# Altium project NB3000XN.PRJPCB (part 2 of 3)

## Sheet FPGA_NonIO.SchDoc: USER FPGA Pwr and Programming
size A4; Organization: Altium Limited.; Address1: Level 3, 12a Rodborough Rd; Address2: Frenchs Forest 2086; Address3: NSW; Address4: AUSTRALIA; DocumentNumber: 8; SheetNumber: 9; SheetTotal: 78
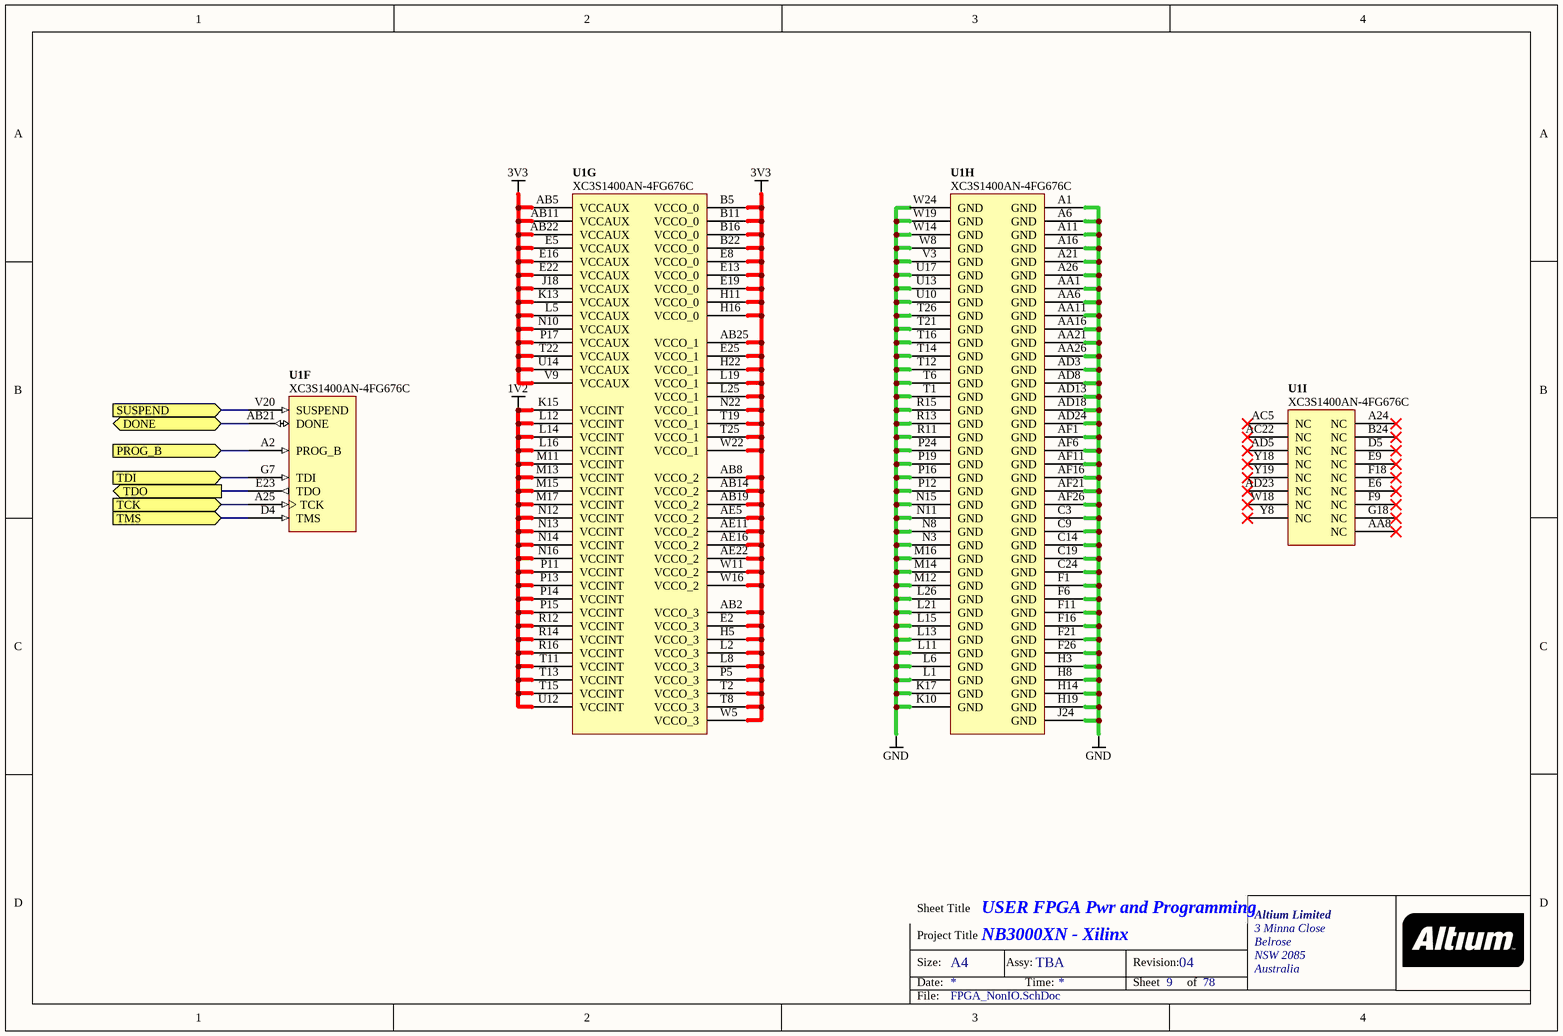
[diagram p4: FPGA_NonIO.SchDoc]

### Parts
(Parts that share a designator on the sheet are numbered #1, #2 ... from top to bottom, then left to right.)
U1#1  XC3S1400AN-4FG676C  [BGA100P26X26-676]  (parts F,G,H,I of 9)

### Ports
DONE (bidir), PROG_B (in), SUSPEND (in), TCK (in), TDI (in), TDO (out), TMS (in)

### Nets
1V2: U1#1.K15(VCCINT) U1#1.L12(VCCINT) U1#1.L14(VCCINT) U1#1.L16(VCCINT) U1#1.M11(VCCINT) U1#1.M13(VCCINT) U1#1.M15(VCCINT) U1#1.M17(VCCINT) U1#1.N12(VCCINT) U1#1.N13(VCCINT) U1#1.N14(VCCINT) U1#1.N16(VCCINT) U1#1.P11(VCCINT) U1#1.P13(VCCINT) U1#1.P14(VCCINT) U1#1.P15(VCCINT) U1#1.R12(VCCINT) U1#1.R14(VCCINT) U1#1.R16(VCCINT) U1#1.T11(VCCINT) U1#1.T13(VCCINT) U1#1.T15(VCCINT) U1#1.U12(VCCINT)
3V3: U1#1.AB2(VCCO_3) U1#1.AB5(VCCAUX) U1#1.AB8(VCCO_2) U1#1.AB11(VCCAUX) U1#1.AB14(VCCO_2) U1#1.AB19(VCCO_2) U1#1.AB22(VCCAUX) U1#1.AB25(VCCO_1) U1#1.AE5(VCCO_2) U1#1.AE11(VCCO_2) U1#1.AE16(VCCO_2) U1#1.AE22(VCCO_2) U1#1.B5(VCCO_0) U1#1.B11(VCCO_0) U1#1.B16(VCCO_0) U1#1.B22(VCCO_0) U1#1.E2(VCCO_3) U1#1.E5(VCCAUX) U1#1.E8(VCCO_0) U1#1.E13(VCCO_0) U1#1.E16(VCCAUX) U1#1.E19(VCCO_0) U1#1.E22(VCCAUX) U1#1.E25(VCCO_1) U1#1.H5(VCCO_3) U1#1.H11(VCCO_0) U1#1.H16(VCCO_0) U1#1.H22(VCCO_1) U1#1.J18(VCCAUX) U1#1.K13(VCCAUX) U1#1.L2(VCCO_3) U1#1.L5(VCCAUX) U1#1.L8(VCCO_3) U1#1.L19(VCCO_1) U1#1.L25(VCCO_1) U1#1.N10(VCCAUX) U1#1.N22(VCCO_1) U1#1.P5(VCCO_3) U1#1.P17(VCCAUX) U1#1.T2(VCCO_3) U1#1.T8(VCCO_3) U1#1.T19(VCCO_1) U1#1.T22(VCCAUX) U1#1.T25(VCCO_1) U1#1.U14(VCCAUX) U1#1.V9(VCCAUX) U1#1.W5(VCCO_3) U1#1.W11(VCCO_2) U1#1.W16(VCCO_2) U1#1.W22(VCCO_1)
GND: U1#1.A1(GND) U1#1.A6(GND) U1#1.A11(GND) U1#1.A16(GND) U1#1.A21(GND) U1#1.A26(GND) U1#1.AA1(GND) U1#1.AA6(GND) U1#1.AA11(GND) U1#1.AA16(GND) U1#1.AA21(GND) U1#1.AA26(GND) U1#1.AD3(GND) U1#1.AD8(GND) U1#1.AD13(GND) U1#1.AD18(GND) U1#1.AD24(GND) U1#1.AF1(GND) U1#1.AF6(GND) U1#1.AF11(GND) U1#1.AF16(GND) U1#1.AF21(GND) U1#1.AF26(GND) U1#1.C3(GND) U1#1.C9(GND) U1#1.C14(GND) U1#1.C19(GND) U1#1.C24(GND) U1#1.F1(GND) U1#1.F6(GND) U1#1.F11(GND) U1#1.F16(GND) U1#1.F21(GND) U1#1.F26(GND) U1#1.H3(GND) U1#1.H8(GND) U1#1.H14(GND) U1#1.H19(GND) U1#1.J24(GND) U1#1.K10(GND) U1#1.K17(GND) U1#1.L1(GND) U1#1.L6(GND) U1#1.L11(GND) U1#1.L13(GND) U1#1.L15(GND) U1#1.L21(GND) U1#1.L26(GND) U1#1.M12(GND) U1#1.M14(GND) U1#1.M16(GND) U1#1.N3(GND) U1#1.N8(GND) U1#1.N11(GND) U1#1.N15(GND) U1#1.P12(GND) U1#1.P16(GND) U1#1.P19(GND) U1#1.P24(GND) U1#1.R11(GND) U1#1.R13(GND) U1#1.R15(GND) U1#1.T1(GND) U1#1.T6(GND) U1#1.T12(GND) U1#1.T14(GND) U1#1.T16(GND) U1#1.T21(GND) U1#1.T26(GND) U1#1.U10(GND) U1#1.U13(GND) U1#1.U17(GND) U1#1.V3(GND) U1#1.V20(SUSPEND) U1#1.W8(GND) U1#1.W14(GND) U1#1.W19(GND) U1#1.W24(GND) ; port SUSPEND
DONE: U1#1.AB21(DONE) ; port DONE
PROG_B: U1#1.A2(PROG_B) ; port PROG_B
TCK: U1#1.A25(TCK) ; port TCK
TDI: U1#1.G7(TDI) ; port TDI
TDO: U1#1.E23(TDO) ; port TDO
TMS: U1#1.D4(TMS) ; port TMS

Not connected (* = marked no-connect by the designer): U1#1 A24(NC)* AA8(NC)* AC5(NC)* AC22(NC)* AD5(NC)* AD23(NC)* B24(NC)* D5(NC)* E6(NC)* E9(NC)* F9(NC)* F18(NC)* G18(NC)* W18(NC)* Y8(NC)* Y18(NC)* Y19(NC)*

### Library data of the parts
U1#1 = D-241-0015: FPGA, Xilinx Spartan 3AN-1400 FG676; Supply Voltage: mV

## Sheet FPGA_Bypass_1V2.SCHDOC: FPGA Bypass 1V2
size A4; Organization: Altium Limited.; Address1: Level 3, 12a Rodborough Rd; Address2: Frenchs Forest 2086; Address3: NSW; Address4: AUSTRALIA; DocumentNumber: 60; SheetNumber: 61; SheetTotal: 78; PageSetup: Record=PageOptions|CenterHorizontal=True|CenterVertical=True|PrintScale=0.97|XCorrection=1.00|YCorrection=1.00|PrintKind=0|BorderSize=5000000|LeftOffset=0|BottomOffset=0|Orientation=2|PaperLength=1000|PaperWidth=1000|Scale=100|PaperSource=7|PrintQuality=-4|MediaType=1|DitherType=10|PaperKind=A4 (210 x 297 mm)|PrintScaleMode=1
Used 2 times, as channels FPGA_USER/USER_DECOUPLING_CAPS_1V2, FPGA_HOST/HOST_DECOUPLING_CAPS_1V2. Parts and nets are listed once, with the designators drawn on the sheet.
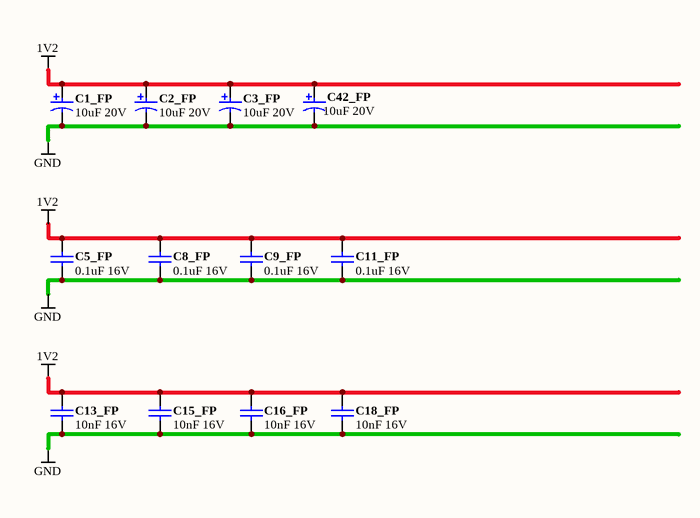
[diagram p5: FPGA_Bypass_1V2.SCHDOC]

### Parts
C1_FP  10uF 20V  [CAPC3528-STAR]
C2_FP  10uF 20V  [CAPC3528-STAR]
C3_FP  10uF 20V  [CAPC3528-STAR]
C5_FP  0.1uF 16V  [CAPC1005-STAR]
C8_FP  0.1uF 16V  [CAPC1005-STAR]
C9_FP  0.1uF 16V  [CAPC1005-STAR]
C11_FP  0.1uF 16V  [CAPC1005-STAR]
C13_FP  10nF 16V  [CAPC1005-STAR]
C15_FP  10nF 16V  [CAPC1005-STAR]
C16_FP  10nF 16V  [CAPC1005-STAR]
C18_FP  10nF 16V  [CAPC1005-STAR]
C42_FP  10uF 20V  [CAPC3528-STAR]

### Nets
1V2: C1_FP.1 C2_FP.1 C3_FP.1 C5_FP.1 C8_FP.1 C9_FP.1 C11_FP.1 C13_FP.1 C15_FP.1 C16_FP.1 C18_FP.1 C42_FP.1
GND: C1_FP.2 C2_FP.2 C3_FP.2 C5_FP.2 C8_FP.2 C9_FP.2 C11_FP.2 C13_FP.2 C15_FP.2 C16_FP.2 C18_FP.2 C42_FP.2

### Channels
FPGA_USER/USER_DECOUPLING_CAPS_1V2: designators end in A
FPGA_HOST/HOST_DECOUPLING_CAPS_1V2: designators end in B

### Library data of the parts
C1_FP C2_FP C3_FP C42_FP = D-101-0007: Capacitor, Tantalum, 10uF 10% 20V MCCT-B (3528); Polarity: Polarized
C5_FP C8_FP C9_FP C11_FP = D-101-0080: Capacitor, Ceramic, 0.1uF 10% 16V 0402 (1005) X7R; Polarity: Non-Polarized
C13_FP C15_FP C16_FP C18_FP = D-101-0077: Capacitor, Ceramic, 10nF 10% 16V 0402 (1005) X7R; Polarity: Non-Polarized

## Sheet FPGA_Bypass_3V3.SCHDOC: FPGA Bypass 3V3
size A4; Organization: Altium Limited.; Address1: Level 3, 12a Rodborough Rd; Address2: Frenchs Forest 2086; Address3: NSW; Address4: AUSTRALIA; DocumentNumber: 58; SheetNumber: 59; SheetTotal: 78; PageSetup: Record=PageOptions|CenterHorizontal=True|CenterVertical=True|PrintScale=0.97|XCorrection=1.00|YCorrection=1.00|PrintKind=0|BorderSize=5000000|LeftOffset=0|BottomOffset=0|Orientation=2|PaperLength=1000|PaperWidth=1000|Scale=100|PaperSource=7|PrintQuality=-4|MediaType=1|DitherType=10|PaperKind=A4 (210 x 297 mm)|PrintScaleMode=1
Used 2 times, as channels FPGA_USER/USER_DECOUPLING_CAPS_3V3, FPGA_HOST/HOST_DECOUPLING_CAPS_3V3. Parts and nets are listed once, with the designators drawn on the sheet.
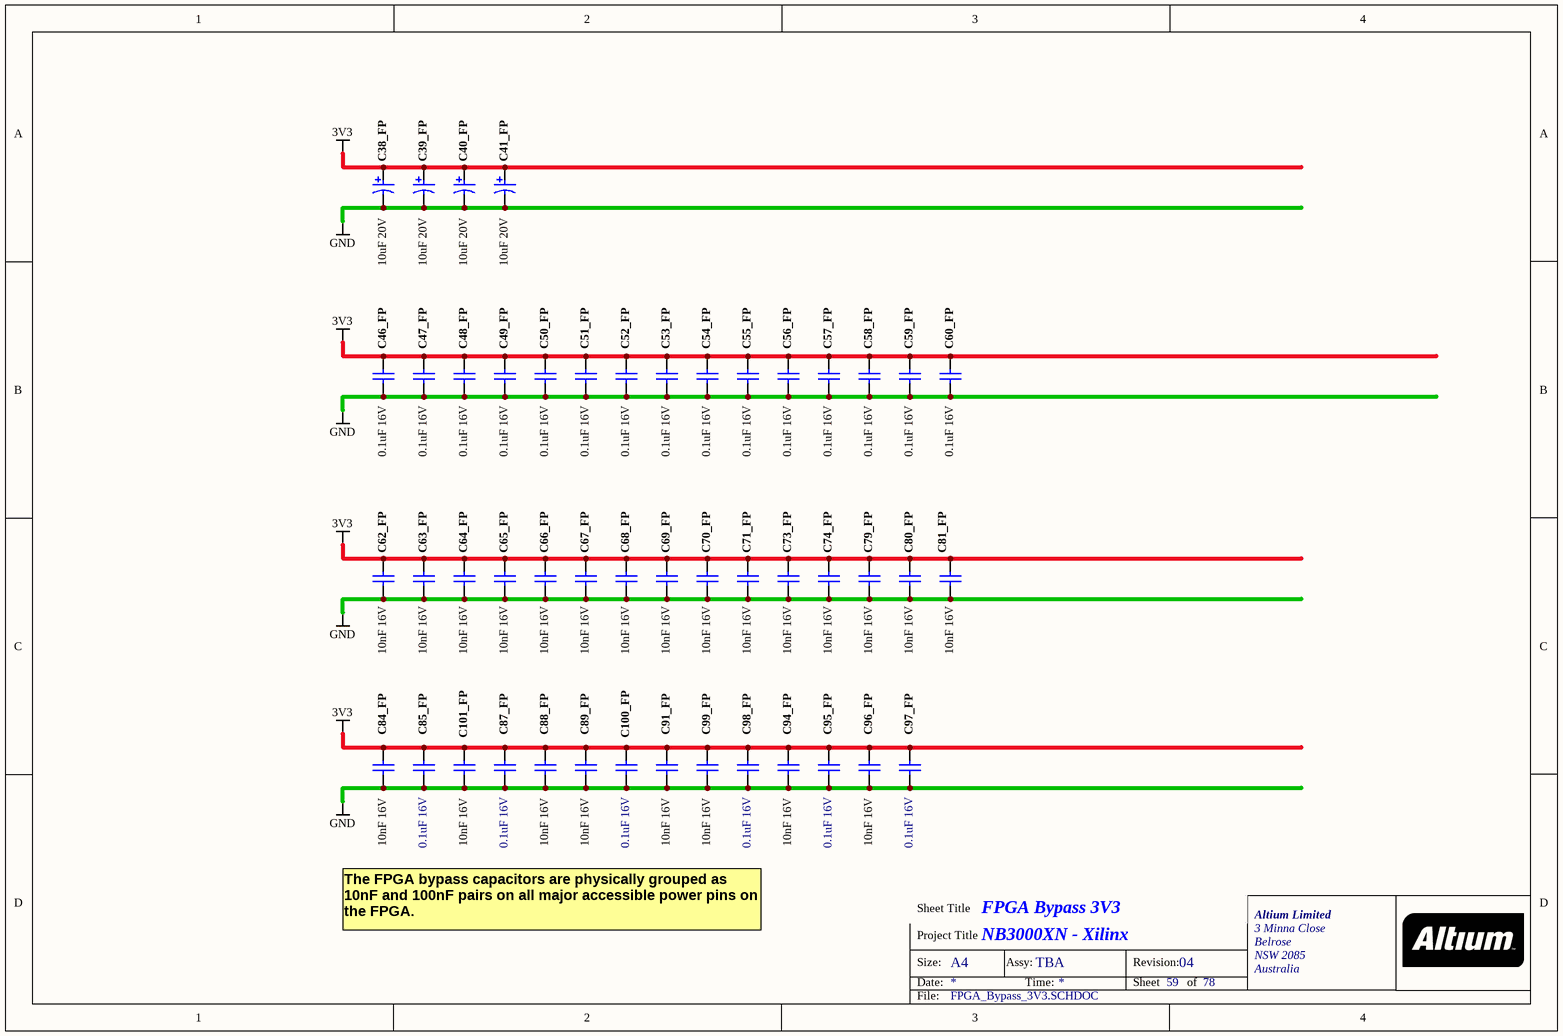
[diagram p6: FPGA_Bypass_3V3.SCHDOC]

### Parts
C38_FP  10uF 20V  [CAPC3528-STAR]
C39_FP  10uF 20V  [CAPC3528-STAR]
C40_FP  10uF 20V  [CAPC3528-STAR]
C41_FP  10uF 20V  [CAPC3528-STAR]
C46_FP  0.1uF 16V  [CAPC1005-STAR]
C47_FP  0.1uF 16V  [CAPC1005-STAR]
C48_FP  0.1uF 16V  [CAPC1005-STAR]
C49_FP  0.1uF 16V  [CAPC1005-STAR]
C50_FP  0.1uF 16V  [CAPC1005-STAR]
C51_FP  0.1uF 16V  [CAPC1005-STAR]
C52_FP  0.1uF 16V  [CAPC1005-STAR]
C53_FP  0.1uF 16V  [CAPC1005-STAR]
C54_FP  0.1uF 16V  [CAPC1005-STAR]
C55_FP  0.1uF 16V  [CAPC1005-STAR]
C56_FP  0.1uF 16V  [CAPC1005-STAR]
C57_FP  0.1uF 16V  [CAPC1005-STAR]
C58_FP  0.1uF 16V  [CAPC1005-STAR]
C59_FP  0.1uF 16V  [CAPC1005-STAR]
C60_FP  0.1uF 16V  [CAPC1005-STAR]
C62_FP  10nF 16V  [CAPC1005-STAR]
C63_FP  10nF 16V  [CAPC1005-STAR]
C64_FP  10nF 16V  [CAPC1005-STAR]
C65_FP  10nF 16V  [CAPC1005-STAR]
C66_FP  10nF 16V  [CAPC1005-STAR]
C67_FP  10nF 16V  [CAPC1005-STAR]
C68_FP  10nF 16V  [CAPC1005-STAR]
C69_FP  10nF 16V  [CAPC1005-STAR]
C70_FP  10nF 16V  [CAPC1005-STAR]
C71_FP  10nF 16V  [CAPC1005-STAR]
C73_FP  10nF 16V  [CAPC1005-STAR]
C74_FP  10nF 16V  [CAPC1005-STAR]
C79_FP  10nF 16V  [CAPC1005-STAR]
C80_FP  10nF 16V  [CAPC1005-STAR]
C81_FP  10nF 16V  [CAPC1005-STAR]
C84_FP  10nF 16V  [CAPC1005-STAR]
C85_FP  0.1uF 16V  [CAPC1005-STAR]
C87_FP  0.1uF 16V  [CAPC1005-STAR]
C88_FP  10nF 16V  [CAPC1005-STAR]
C89_FP  10nF 16V  [CAPC1005-STAR]
C91_FP  10nF 16V  [CAPC1005-STAR]
C94_FP  10nF 16V  [CAPC1005-STAR]
C95_FP  0.1uF 16V  [CAPC1005-STAR]
C96_FP  10nF 16V  [CAPC1005-STAR]
C97_FP  0.1uF 16V  [CAPC1005-STAR]
C98_FP  0.1uF 16V  [CAPC1005-STAR]
C99_FP  10nF 16V  [CAPC1005-STAR]
C100_FP  0.1uF 16V  [CAPC1005-STAR]
C101_FP  10nF 16V  [CAPC1005-STAR]

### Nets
3V3: C38_FP.1 C39_FP.1 C40_FP.1 C41_FP.1 C46_FP.1 C47_FP.1 C48_FP.1 C49_FP.1 C50_FP.1 C51_FP.1 C52_FP.1 C53_FP.1 C54_FP.1 C55_FP.1 C56_FP.1 C57_FP.1 C58_FP.1 C59_FP.1 C60_FP.1 C62_FP.1 C63_FP.1 C64_FP.1 C65_FP.1 C66_FP.1 C67_FP.1 C68_FP.1 C69_FP.1 C70_FP.1 C71_FP.1 C73_FP.1 C74_FP.1 C79_FP.1 C80_FP.1 C81_FP.1 C84_FP.1 C85_FP.1 C87_FP.1 C88_FP.1 C89_FP.1 C91_FP.1 C94_FP.1 C95_FP.1 C96_FP.1 C97_FP.1 C98_FP.1 C99_FP.1 C100_FP.1 C101_FP.1
GND: C38_FP.2 C39_FP.2 C40_FP.2 C41_FP.2 C46_FP.2 C47_FP.2 C48_FP.2 C49_FP.2 C50_FP.2 C51_FP.2 C52_FP.2 C53_FP.2 C54_FP.2 C55_FP.2 C56_FP.2 C57_FP.2 C58_FP.2 C59_FP.2 C60_FP.2 C62_FP.2 C63_FP.2 C64_FP.2 C65_FP.2 C66_FP.2 C67_FP.2 C68_FP.2 C69_FP.2 C70_FP.2 C71_FP.2 C73_FP.2 C74_FP.2 C79_FP.2 C80_FP.2 C81_FP.2 C84_FP.2 C85_FP.2 C87_FP.2 C88_FP.2 C89_FP.2 C91_FP.2 C94_FP.2 C95_FP.2 C96_FP.2 C97_FP.2 C98_FP.2 C99_FP.2 C100_FP.2 C101_FP.2

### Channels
FPGA_USER/USER_DECOUPLING_CAPS_3V3: designators end in A
FPGA_HOST/HOST_DECOUPLING_CAPS_3V3: designators end in B

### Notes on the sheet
- The FPGA bypass capacitors are physically grouped as 10nF and 100nF pairs on all major accessible power pins on the FPGA.

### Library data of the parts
C38_FP C39_FP C40_FP C41_FP = D-101-0007: as C1_FP on sheet FPGA_Bypass_1V2
C46_FP C47_FP C48_FP C49_FP C50_FP C51_FP C52_FP C53_FP C54_FP C55_FP C56_FP C57_FP C58_FP C59_FP C60_FP C85_FP C87_FP C95_FP C97_FP C98_FP C100_FP = D-101-0080: as C5_FP on sheet FPGA_Bypass_1V2
C62_FP C63_FP C64_FP C65_FP C66_FP C67_FP C68_FP C69_FP C70_FP C71_FP C73_FP C74_FP C79_FP C80_FP C81_FP C84_FP C88_FP C89_FP C91_FP C94_FP C96_FP C99_FP C101_FP = D-101-0077: as C13_FP on sheet FPGA_Bypass_1V2

## Sheet VGA_OUT.SCHDOC: VGA Ouput
size A4; DocumentNumber: 2; SheetNumber: 3; SheetTotal: 78; PageSetup: Record=PageOptions|CenterHorizontal=True|CenterVertical=True|PrintScale=0.97|XCorrection=1.00|YCorrection=1.00|PrintKind=1|BorderSize=5000000|LeftOffset=0|BottomOffset=0|Orientation=2|PaperLength=1000|PaperWidth=1000|Scale=100|PaperSource=7|PrintQuality=-4|MediaType=1|DitherType=10|PaperKind=A4 (210 x 297 mm)|PrintScaleMode=1
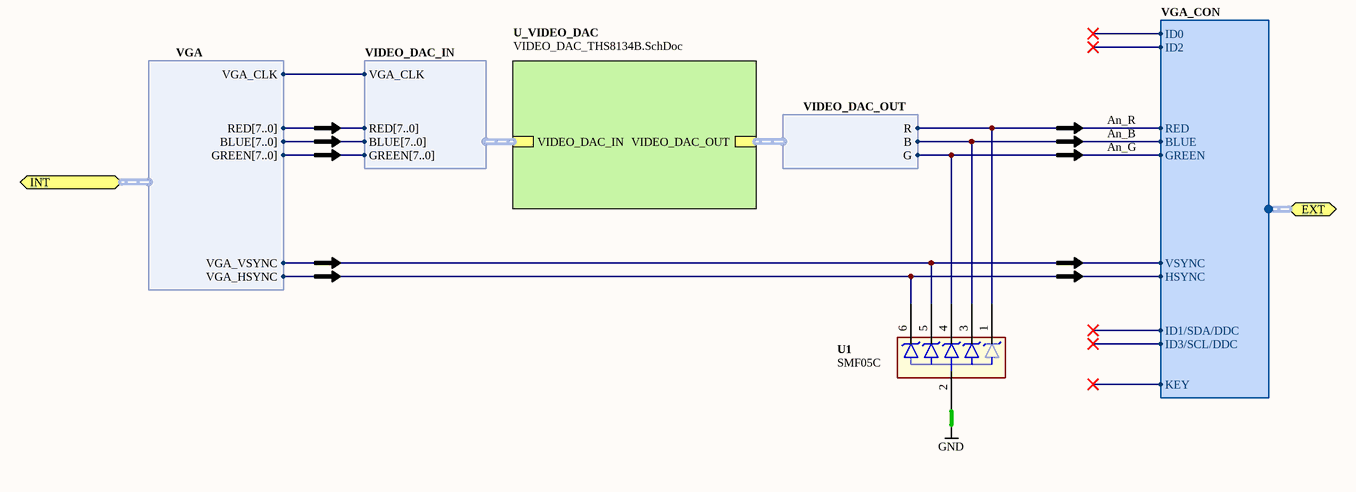
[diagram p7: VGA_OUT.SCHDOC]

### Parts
(Parts that share a designator on the sheet are numbered #1, #2 ... from top to bottom, then left to right.)
U1#2  SMF05C  [SC70_6L]

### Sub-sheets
U_VIDEO_DAC = VIDEO_DAC_THS8134B.SchDoc: VIDEO_DAC_OUT (harness VIDEO_DAC_OUT), VIDEO_DAC_IN (harness VIDEO_DAC_IN)

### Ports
EXT (harness VGA_CON), INT (harness VGA)

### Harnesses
VIDEO_DAC_IN: RED[7..0], GREEN[7..0], BLUE[7..0], VGA_CLK
VIDEO_DAC_OUT: B, R, G
VGA: RED[7..0], GREEN[7..0], BLUE[7..0], VGA_CLK, VGA_VSYNC, VGA_HSYNC
VGA_CON: RED, GREEN, BLUE, VSYNC, HSYNC, KEY, ID2, ID3/SCL/DDC, ID1/SDA/DDC, ID0

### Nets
GND: U1#2.2
An_B: U1#2.3 ; sheet U_VIDEO_DAC/VIDEO_DAC_OUT.B, port EXT.BLUE  [project net VGA#.BLUE]
An_G: U1#2.4 ; sheet U_VIDEO_DAC/VIDEO_DAC_OUT.G, port EXT.GREEN  [project net VGA#.GREEN]
An_R: U1#2.1 ; sheet U_VIDEO_DAC/VIDEO_DAC_OUT.R, port EXT.RED  [project net VGA#.RED]
VGA#.HSYNC: U1#2.6 ; port INT.VGA_HSYNC, port EXT.HSYNC
VGA#.VSYNC: U1#2.5 ; port INT.VGA_VSYNC, port EXT.VSYNC
VGA.VGA_CLK: sheet U_VIDEO_DAC/VIDEO_DAC_IN.VGA_CLK, port INT.VGA_CLK

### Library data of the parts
U1#2 = D-157-0000: TVS Diode Array  For ESD and Latch-Up Protection; Junction Capacitance: 130 pF; Peak Pulse Current: 8 A; Peak Pulse Power: 100 W; Reverse Breakdown Voltage: 6 V

## Sheet VIDEO_DAC_THS8134B.SchDoc: Video DAC
size A4; Organization: Altium Limited.; Address1: Level 3, 12a Rodborough Rd; Address2: Frenchs Forest 2086; Address3: NSW; Address4: AUSTRALIA; DocumentNumber: 62; SheetNumber: 63; SheetTotal: 78
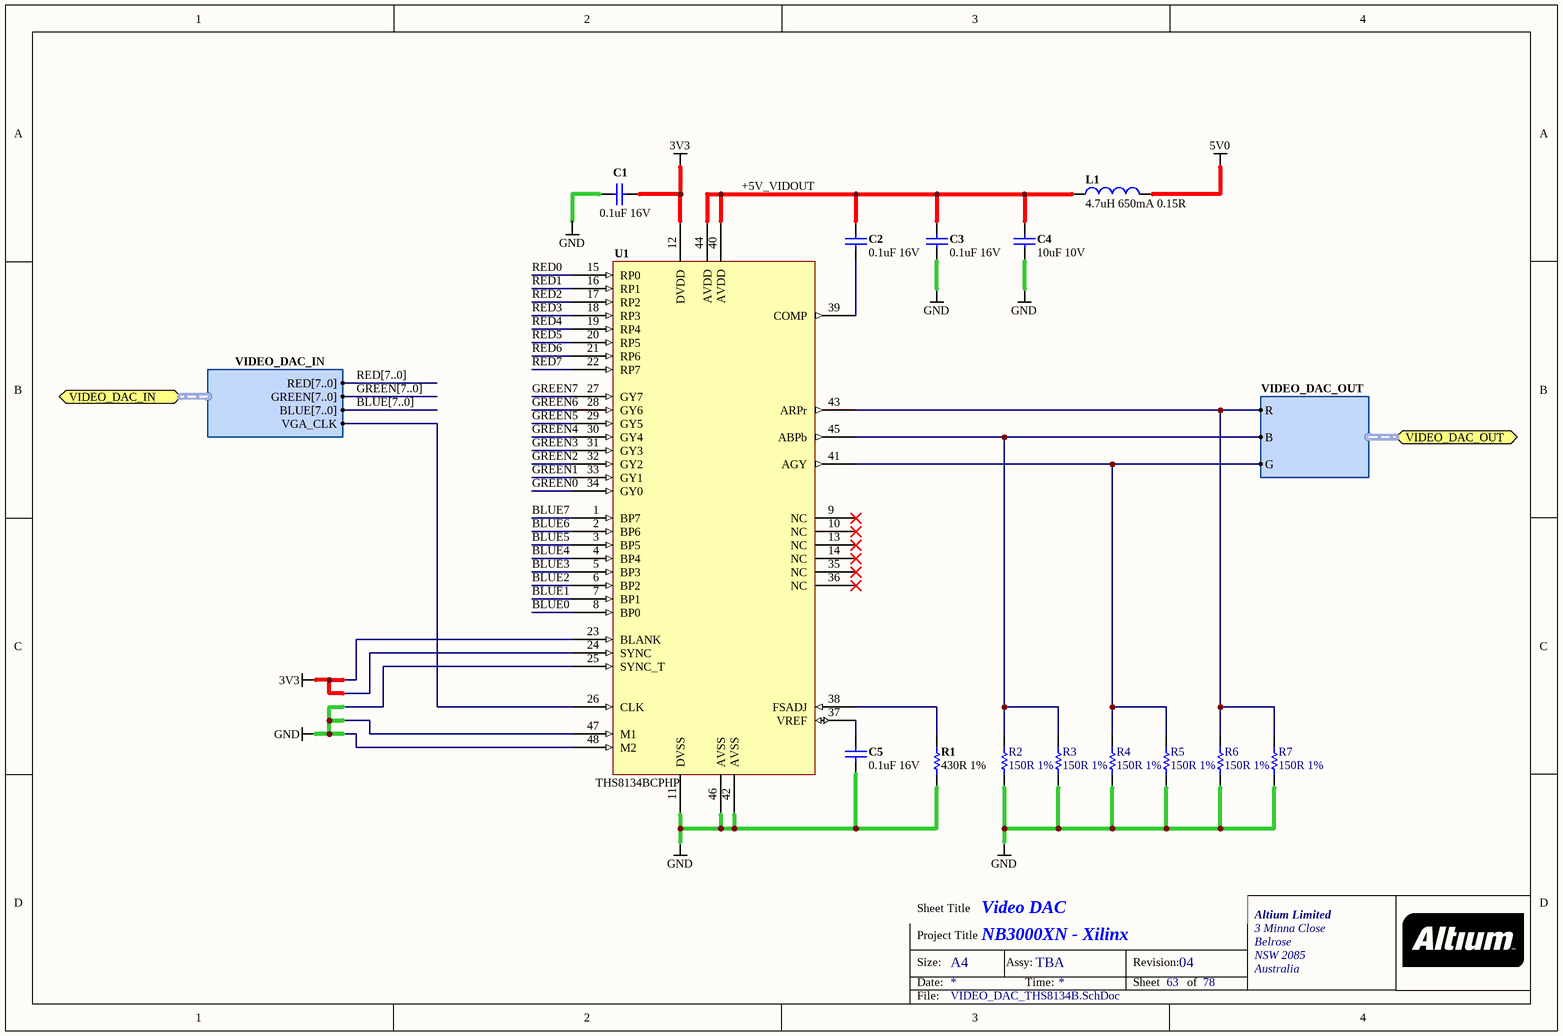
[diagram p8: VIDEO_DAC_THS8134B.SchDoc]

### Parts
(Parts that share a designator on the sheet are numbered #1, #2 ... from top to bottom, then left to right.)
C1#2  0.1uF 16V  [CAPC1005-STAR]
C2#2  0.1uF 16V  [CAPC1005-STAR]
C3#2  0.1uF 16V  [CAPC1005-STAR]
C4#2  10uF 10V  [CAPC2012-STAR]
C5#1  0.1uF 16V  [CAPC1005-STAR]
L1#1  4.7uH 650mA 0.15R  [INDC3225]
R1#2  430R 1%  [RESC1005-STAR]
R2#2  150R 1%  [RESC1005-STAR]
R3#2  150R 1%  [RESC1005-STAR]
R4#2  150R 1%  [RESC1005-STAR]
R5#1  150R 1%  [RESC1005-STAR]
R6#1  150R 1%  [RESC1005-STAR]
R7#1  150R 1%  [RESC1005-STAR]
U1#3  THS8134BCPHP  [TSQFP50P900X900_HS-48]

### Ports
VIDEO_DAC_IN (harness VIDEO_DAC_IN), VIDEO_DAC_OUT (harness VIDEO_DAC_OUT)

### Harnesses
VIDEO_DAC_OUT: B, R, G
VIDEO_DAC_IN: RED[7..0], GREEN[7..0], BLUE[7..0], VGA_CLK

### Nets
3V3: C1#2.1 U1#3.12(DVDD) U1#3.23(BLANK) U1#3.24(SYNC)
5V0: L1#1.1
GND: C1#2.2 C3#2.2 C4#2.1 C5#1.2 R1#2.1 R2#2.2 R3#2.1 R4#2.2 R5#1.1 R6#1.1 R7#1.1 U1#3.11(DVSS) U1#3.25(SYNC_T) U1#3.42(AVSS) U1#3.46(AVSS) U1#3.47(M1) U1#3.48(M2)
+5V_VIDOUT: C2#2.1 C3#2.1 C4#2.2 L1#1.2 U1#3.40(AVDD) U1#3.44(AVDD)
BLUE0: U1#3.8(BP0)  [project net VGA_BLUE0]
BLUE1: U1#3.7(BP1)  [project net VGA_BLUE1]
BLUE2: U1#3.6(BP2)  [project net VGA_BLUE2]
BLUE3: U1#3.5(BP3)  [project net VGA_BLUE3]
BLUE4: U1#3.4(BP4)  [project net VGA_BLUE4]
BLUE5: U1#3.3(BP5)  [project net VGA_BLUE5]
BLUE6: U1#3.2(BP6)  [project net VGA_BLUE6]
BLUE7: U1#3.1(BP7)  [project net VGA_BLUE7]
GREEN0: U1#3.34(GY0)  [project net VGA_GREEN0]
GREEN1: U1#3.33(GY1)  [project net VGA_GREEN1]
GREEN2: U1#3.32(GY2)  [project net VGA_GREEN2]
GREEN3: U1#3.31(GY3)  [project net VGA_GREEN3]
GREEN4: U1#3.30(GY4)  [project net VGA_GREEN4]
GREEN5: U1#3.29(GY5)  [project net VGA_GREEN5]
GREEN6: U1#3.28(GY6)  [project net VGA_GREEN6]
GREEN7: U1#3.27(GY7)  [project net VGA_GREEN7]
RED0: U1#3.15(RP0)  [project net VGA_RED0]
RED1: U1#3.16(RP1)  [project net VGA_RED1]
RED2: U1#3.17(RP2)  [project net VGA_RED2]
RED3: U1#3.18(RP3)  [project net VGA_RED3]
RED4: U1#3.19(RP4)  [project net VGA_RED4]
RED5: U1#3.20(RP5)  [project net VGA_RED5]
RED6: U1#3.21(RP6)  [project net VGA_RED6]
RED7: U1#3.22(RP7)  [project net VGA_RED7]
VGA#.BLUE: R2#2.1 R3#2.2 U1#3.45(ABPb) ; port VIDEO_DAC_OUT.B
VGA#.GREEN: R4#2.1 R5#1.2 U1#3.41(AGY) ; port VIDEO_DAC_OUT.G
VGA#.RED: R6#1.2 R7#1.2 U1#3.43(ARPr) ; port VIDEO_DAC_OUT.R
VGA.VGA_CLK: U1#3.26(CLK) ; port VIDEO_DAC_IN.VGA_CLK
NetC2#2_2: C2#2.2 U1#3.39(COMP)
NetC5#1_1: C5#1.1 U1#3.37(VREF)
NetR1#2_2: R1#2.2 U1#3.38(FSADJ)

Not connected (* = marked no-connect by the designer): U1#3 9(NC)* 10(NC)* 13(NC)* 14(NC)* 35(NC)* 36(NC)*

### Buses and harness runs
bus BLUE[7..0]
bus GREEN[7..0]
bus RED[7..0]

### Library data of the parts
C1#2 C2#2 C3#2 C5#1 = D-101-0080: as C5_FP on sheet FPGA_Bypass_1V2
C4#2 = D-101-0087: Capacitor, Ceramic, 10uF 10% 10V 0805 (2012) X5R; Polarity: Non-Polarized
L1#1 = D-102-0005: Inductor, 4.7uH 650mA 0.15R 1210 (3225) LQH32CN4R7M11L
R1#2 = D-100-0096: Resistor, 430R 1% 0402 (1005); Power Rating: 63 mW
R2#2 R3#2 R4#2 R5#1 R6#1 R7#1 = D-100-0005: Resistor, 150R 1% 0402 (1005); Power Rating: 63mW
U1#3 = D-222-0000: THS8134BCPHP, Triple 8-Bit, 80 MSPS Video DAC with Tri-Level Sync Generation

## Sheet Host_FPGA.SchDoc: Host Controller - Spartan3AN-400
size A2; Organization: Altium Limited.; Address1: Level 3, 12a Rodborough Rd; Address2: Frenchs Forest 2086; Address3: NSW; Address4: AUSTRALIA; DocumentNumber: 28; Revision: 6; SheetNumber: 29; SheetTotal: 78; PageSetup: Record=PageOptions|CenterHorizontal=True|CenterVertical=True|PrintScale=0.47|XCorrection=1.00|YCorrection=1.00|PrintKind=0|BorderSize=5000000|LeftOffset=0|BottomOffset=0|Orientation=2|PaperLength=1000|PaperWidth=1000|Scale=100|PaperSource=7|PrintQuality=1200|MediaType=1|DitherType=10|PaperKind=A4 (210 x 297 mm)|PrintScaleMode=1
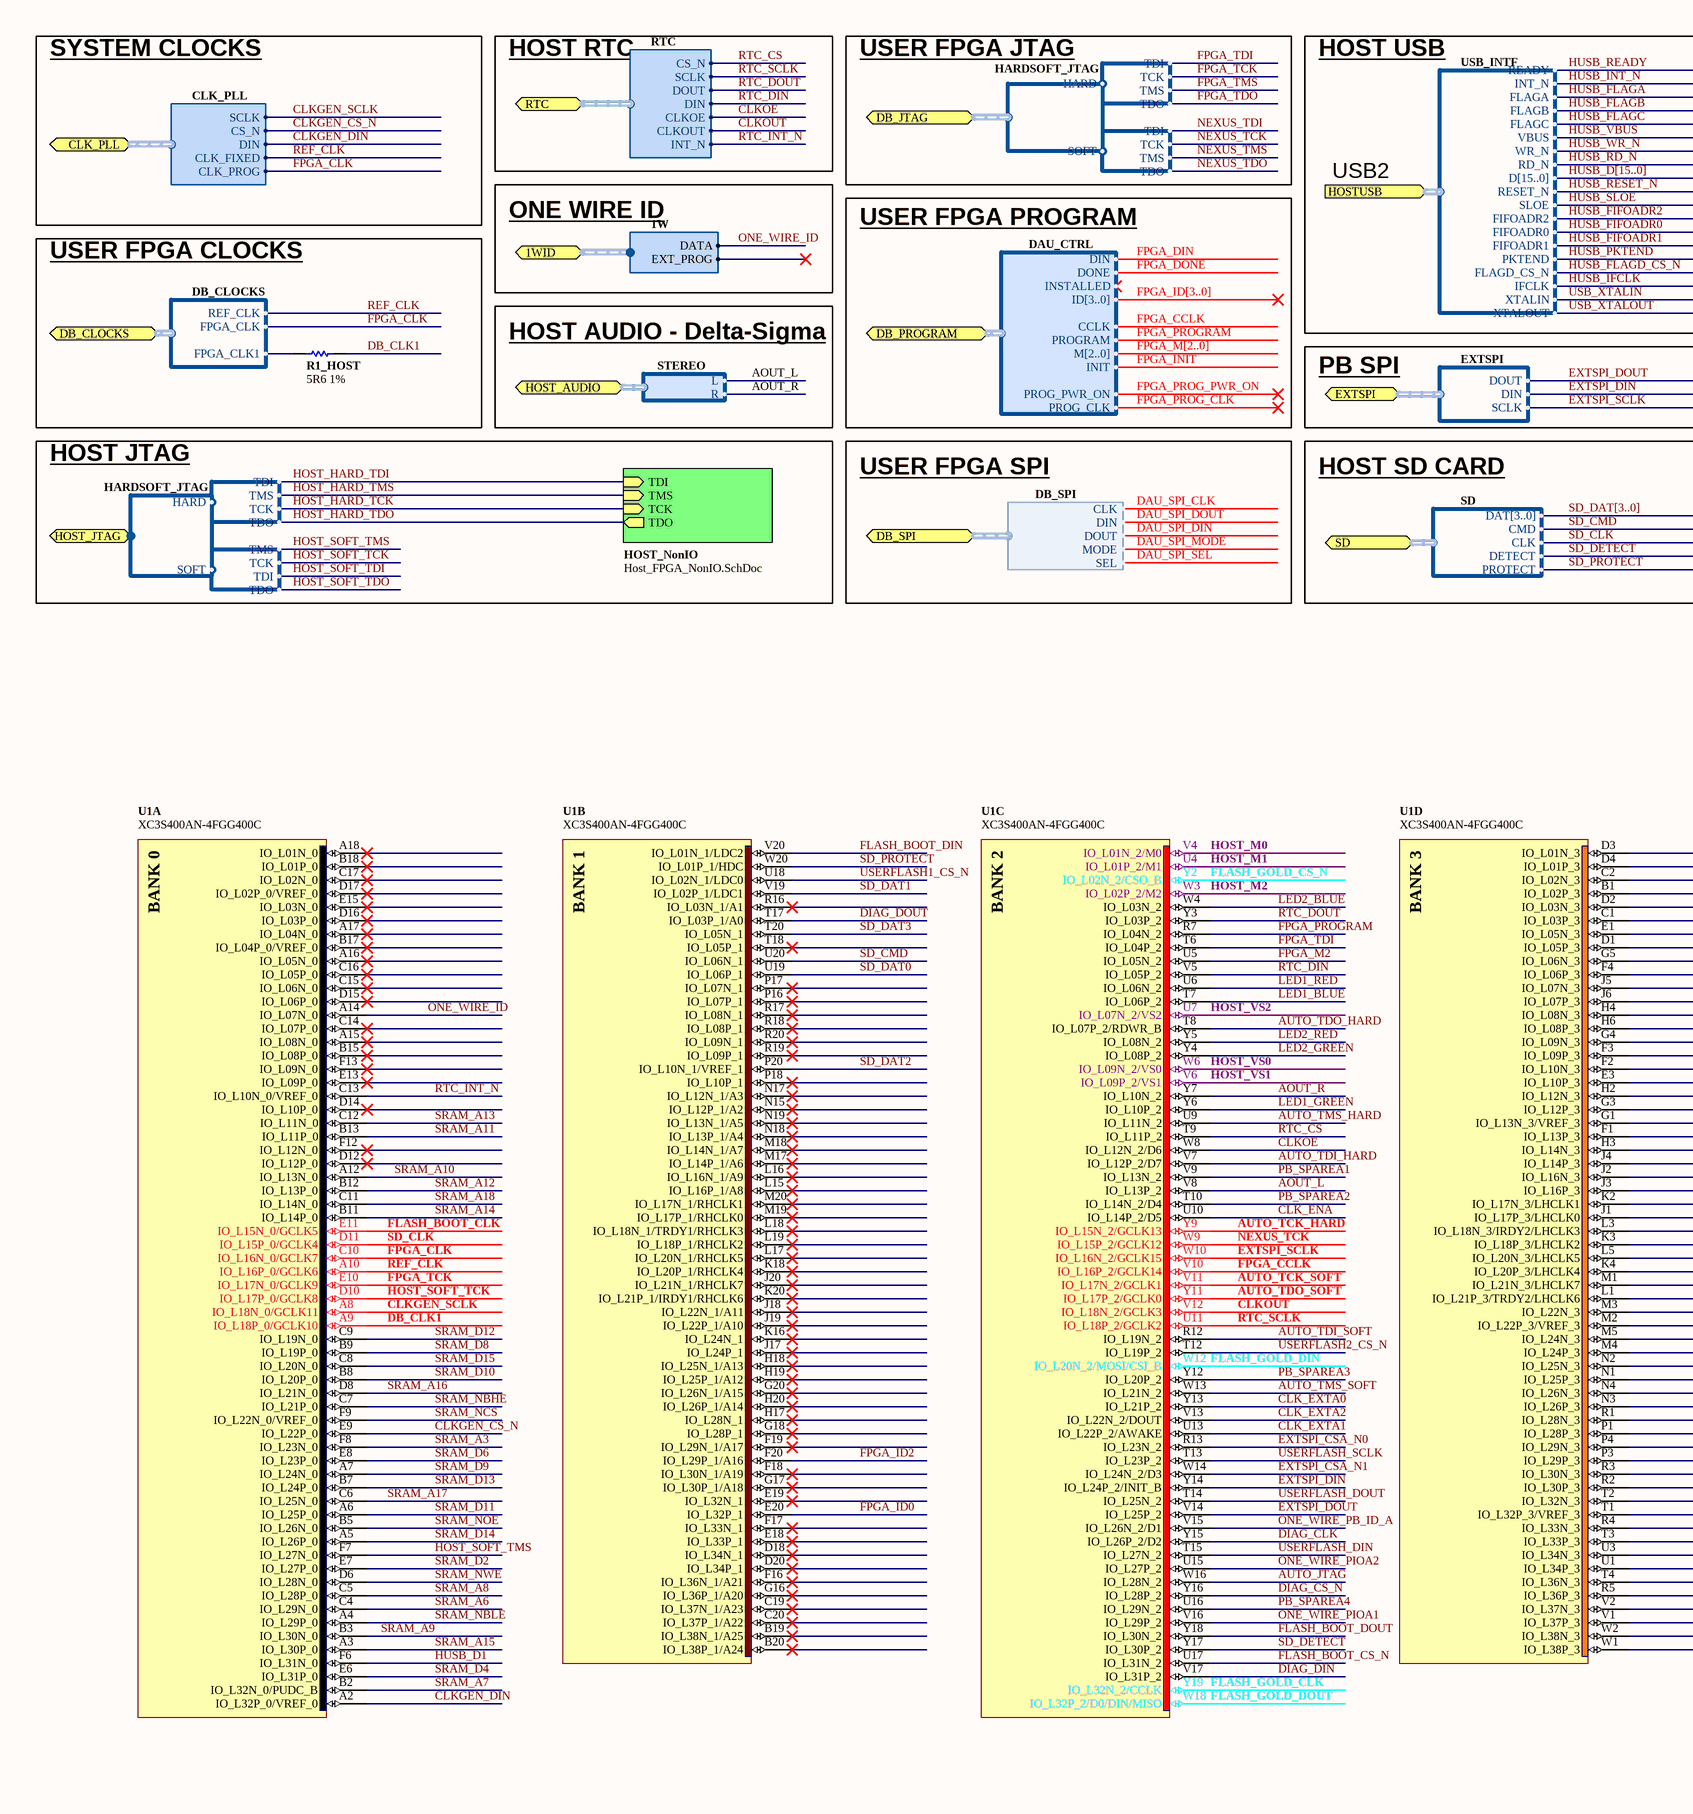
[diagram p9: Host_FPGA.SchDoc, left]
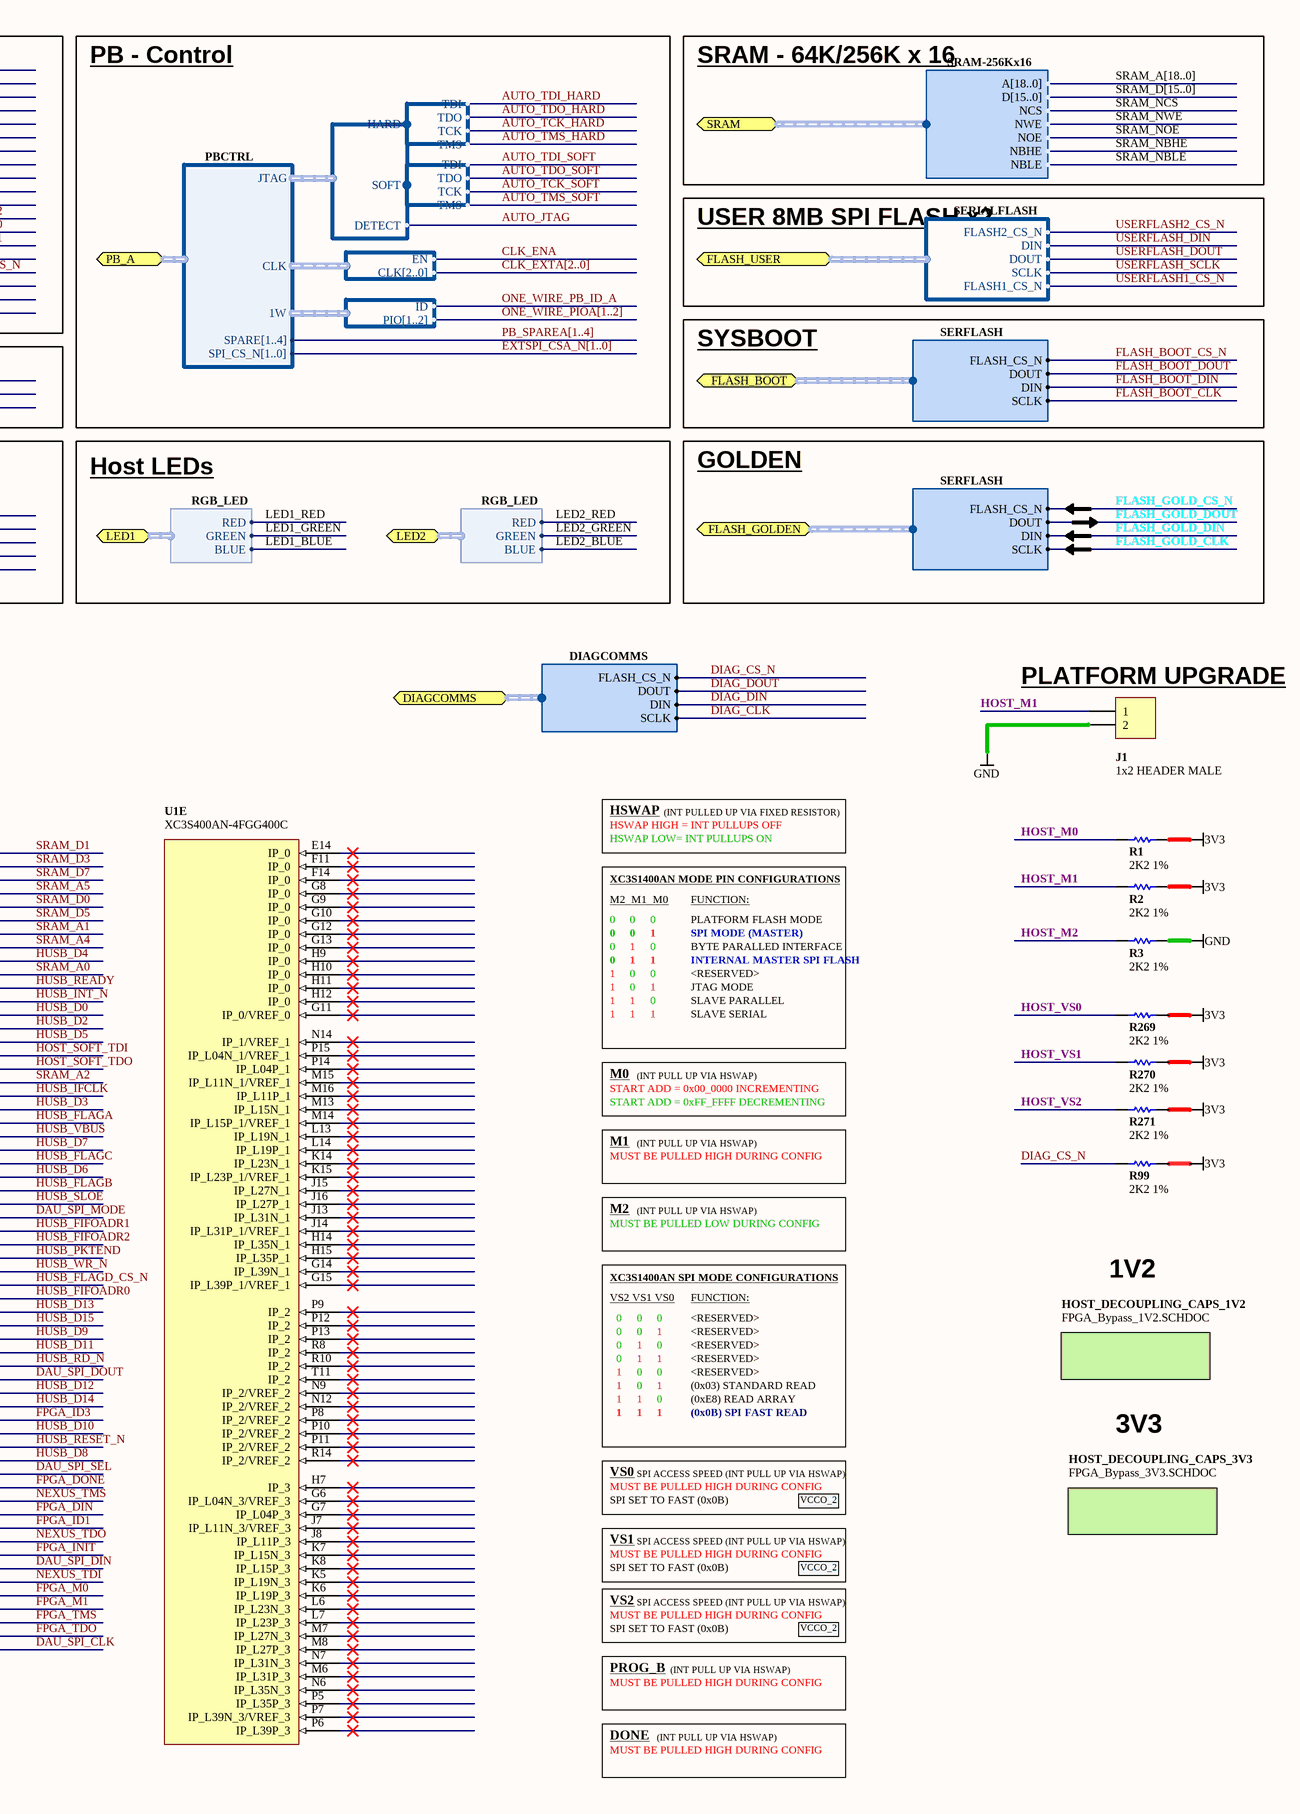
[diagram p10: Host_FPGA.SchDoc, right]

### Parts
(Parts that share a designator on the sheet are numbered #1, #2 ... from top to bottom, then left to right.)
J1#2  1x2 HEADER MALE  [HDR1X2]
R1#3  2K2 1%  [RESC1005-STAR]
R1_HOST  5R6 1%  [RESC1005-STAR]
R2#3  2K2 1%  [RESC1005-STAR]
R3#3  2K2 1%  [RESC1005-STAR]
R99  2K2 1%  [RESC1005-STAR]
R269  2K2 1%  [RESC1005-STAR]
R270  2K2 1%  [RESC1005-STAR]
R271  2K2 1%  [RESC1005-STAR]
U1#4  XC3S400AN-4FGG400C  [FGG400]  (parts A,B,C,D,E of 8)

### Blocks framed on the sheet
USER FPGA CLOCKS: R1_HOST

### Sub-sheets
HOST_DECOUPLING_CAPS_1V2 = FPGA_Bypass_1V2.SCHDOC: no entries
HOST_DECOUPLING_CAPS_3V3 = FPGA_Bypass_3V3.SCHDOC: no entries
HOST_NonIO = Host_FPGA_NonIO.SchDoc: TMS (in), TCK (in), TDI (in), TDO (out)

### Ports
1WID (harness 1W), CLK_PLL (harness CLK_PLL), DB_CLOCKS (harness DB_CLOCKS), DB_JTAG (harness HARDSOFT_JTAG), DB_PROGRAM (harness DAU_CTRL), DB_SPI (harness DB_SPI), DIAGCOMMS (harness DIAGCOMMS), EXTSPI (harness EXTSPI), FLASH_BOOT (harness SERFLASH), FLASH_GOLDEN (harness SERFLASH), FLASH_USER (harness SERIALFLASH), HOST_AUDIO (harness STEREO), HOST_JTAG (harness HARDSOFT_JTAG), HOSTUSB (harness USB_INTF), LED1 (harness RGB_LED), LED2 (harness RGB_LED), PB_A (harness PBCTRL), RTC (harness RTC), SD (harness SD), SRAM (harness SRAM-256Kx16)

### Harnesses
SERIALFLASH: FLASH2_CS_N, DIN, DOUT, SCLK, FLASH1_CS_N
JTAG: TMS, TDO, TDI, TCK
HARDSOFT_JTAG: HARD, SOFT
SD: DAT[3..0], CMD, CLK, DETECT, PROTECT
STEREO: L, R
RTC: CS_N, DIN, DOUT, INT_N, SCLK, CLKOUT, CLKOE
DAU_CTRL: DIN, DONE, INSTALLED, ID[3..0], CCLK, PROGRAM, M[2..0], INIT, PROG_PWR_ON, PROG_CLK
1W: DATA, EXT_PROG
CLK_PLL: CLK_FIXED, CLK_PROG, CS_N, DIN, SCLK
SRAM-256Kx16: A[18..0], D[15..0], NCS, NWE, NOE, NBHE, NBLE
RGB_LED: GREEN, RED, BLUE
DB_CLOCKS: REF_CLK, FPGA_CLK, FPGA_CLK1
DB_SPI: MODE, SEL, CLK, DIN, DOUT
JTAG_CONFIG: HARD, SOFT, DETECT
JTAG: TDI, TDO, TCK, TMS
GATE_CLOCKS: EN, CLK[2..0]
ONE_WIRE: ID, PIO[1..2]
PBCTRL: JTAG, CLK, 1W, SPI_CS_N[1..0], SPARE[1..4]
EXTSPI: DOUT, DIN, SCLK
SERFLASH: DIN, DOUT, SCLK, FLASH_CS_N
USB_INTF: READY, INT_N, SLOE, FIFOADR2, FIFOADR0, FIFOADR1, PKTEND, FLAGD_CS_N, FLAGA, FLAGB, FLAGC, WR_N, RD_N, D[15..0], RESET_N, IFCLK, XTALIN, VBUS, XTALOUT
DIAGCOMMS: DIN, DOUT, SCLK, FLASH_CS_N

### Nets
3V3: R1#3.2 R2#3.2 R99.2 R269.2 R270.2 R271.2
GND: J1#2.2 R3#3.2
AOUT_L: U1#4.V8(IO_L13P_2) ; port HOST_AUDIO.L  [project net HOST_AUDIO.L]
AOUT_R: U1#4.Y7(IO_L10N_2) ; port HOST_AUDIO.R  [project net HOST_AUDIO.R]
AUTO_JTAG: U1#4.W16(IO_L28N_2) ; harness JTAG_CONFIG.DETECT
AUTO_TCK_HARD: U1#4.Y9(IO_L15N_2/GCLK13) ; harness JTAG.TCK
AUTO_TCK_SOFT: U1#4.V11(IO_L17N_2/GCLK1) ; harness JTAG.TCK
AUTO_TDI_HARD: U1#4.V7(IO_L12P_2/D7) ; harness JTAG.TDI
AUTO_TDI_SOFT: U1#4.R12(IO_L19N_2) ; harness JTAG.TDI
AUTO_TDO_HARD: U1#4.T8(IO_L07P_2/RDWR_B) ; harness JTAG.TDO
AUTO_TDO_SOFT: U1#4.Y11(IO_L17P_2/GCLK0) ; harness JTAG.TDO
AUTO_TMS_HARD: U1#4.U9(IO_L11N_2) ; harness JTAG.TMS
AUTO_TMS_SOFT: U1#4.W13(IO_L21N_2) ; harness JTAG.TMS
CLK_ENA: U1#4.U10(IO_L14P_2/D5) ; harness GATE_CLOCKS.EN
CLK_EXTA0: U1#4.Y13(IO_L21P_2)
CLK_EXTA1: U1#4.U13(IO_L22P_2/AWAKE)
CLK_EXTA2: U1#4.V13(IO_L22N_2/DOUT)
CLKGEN_CS_N: U1#4.E9(IO_L22P_0) ; port CLK_PLL.CS_N  [project net HOST_CLK.CS_N]
CLKGEN_DIN: U1#4.A2(IO_L32P_0/VREF_0) ; port CLK_PLL.DIN  [project net HOST_CLK.DIN]
CLKGEN_SCLK: U1#4.A8(IO_L18N_0/GCLK11) ; port CLK_PLL.SCLK  [project net HOST_CLK.SCLK]
CLKOE: U1#4.W8(IO_L12N_2/D6) ; port RTC.CLKOE  [project net HOST_RTC.CLKOE]
CLKOUT: U1#4.V12(IO_L18N_2/GCLK3) ; port RTC.CLKOUT  [project net HOST_RTC.CLKOUT]
DAU_SPI_CLK: U1#4.W1(IO_L38P_3) ; port DB_SPI.CLK  [project net DB_SPI.CLK]
DAU_SPI_DIN: U1#4.U1(IO_L34P_3) ; port DB_SPI.DOUT  [project net DB_SPI.DOUT]
DAU_SPI_DOUT: U1#4.N1(IO_L25P_3) ; port DB_SPI.DIN  [project net DB_SPI.DIN]
DAU_SPI_MODE: U1#4.J1(IO_L17P_3/LHCLK0) ; port DB_SPI.MODE  [project net DB_SPI.MODE]
DAU_SPI_SEL: U1#4.R3(IO_L30N_3) ; port DB_SPI.SEL  [project net DB_SPI.SEL]
DB_CLK1: R1_HOST.1 U1#4.A9(IO_L18P_0/GCLK10)
DB_CLOCKS.FPGA_CLK1: R1_HOST.2 ; port DB_CLOCKS.FPGA_CLK1
DIAG_CLK: U1#4.Y15(IO_L26P_2/D2) ; port DIAGCOMMS.SCLK  [project net DIAGCOMMS.SCLK]
DIAG_CS_N: R99.1 U1#4.Y16(IO_L28P_2) ; port DIAGCOMMS.FLASH_CS_N  [project net DIAGCOMMS.FLASH_CS_N]
DIAG_DIN: U1#4.V17(IO_L31P_2) ; port DIAGCOMMS.DIN  [project net DIAGCOMMS.DIN]
DIAG_DOUT: U1#4.T17(IO_L03P_1/A0) ; port DIAGCOMMS.DOUT  [project net DIAGCOMMS.DOUT]
EXTSPI_CSA_N0: U1#4.R13(IO_L23N_2)
EXTSPI_CSA_N1: U1#4.W14(IO_L24N_2/D3)
EXTSPI_DIN: U1#4.Y14(IO_L24P_2/INIT_B) ; port EXTSPI.DIN  [project net PB_SPI.DIN]
EXTSPI_DOUT: U1#4.V14(IO_L25P_2) ; port EXTSPI.DOUT  [project net PB_SPI.DOUT]
EXTSPI_SCLK: U1#4.W10(IO_L16N_2/GCLK15) ; port EXTSPI.SCLK  [project net PB_SPI.SCLK]
FLASH_BOOT_CLK: U1#4.E11(IO_L15N_0/GCLK5) ; port FLASH_BOOT.SCLK  [project net BOOT_FLASH.SCLK]
FLASH_BOOT_CS_N: U1#4.U17(IO_L31N_2) ; port FLASH_BOOT.FLASH_CS_N  [project net BOOT_FLASH.FLASH_CS_N]
FLASH_BOOT_DIN: U1#4.V20(IO_L01N_1/LDC2) ; port FLASH_BOOT.DIN  [project net BOOT_FLASH.DIN]
FLASH_BOOT_DOUT: U1#4.Y18(IO_L30N_2) ; port FLASH_BOOT.DOUT  [project net BOOT_FLASH.DOUT]
FLASH_GOLD_CLK: U1#4.Y19(IO_L32N_2/CCLK) ; port FLASH_GOLDEN.SCLK  [project net GOLD_FLASH.SCLK]
FLASH_GOLD_CS_N: U1#4.Y2(IO_L02N_2/CSO_B) ; port FLASH_GOLDEN.FLASH_CS_N  [project net GOLD_FLASH.FLASH_CS_N]
FLASH_GOLD_DIN: U1#4.W12(IO_L20N_2/MOSI/CSI_B) ; port FLASH_GOLDEN.DIN  [project net GOLD_FLASH.DIN]
FLASH_GOLD_DOUT: U1#4.W18(IO_L32P_2/D0/DIN/MISO) ; port FLASH_GOLDEN.DOUT  [project net GOLD_FLASH.DOUT]
FPGA_CCLK: U1#4.V10(IO_L16P_2/GCLK14) ; port DB_PROGRAM.CCLK  [project net DB_PROGRAM.CCLK]
FPGA_CLK: U1#4.C10(IO_L16N_0/GCLK7) ; port CLK_PLL.CLK_PROG, port DB_CLOCKS.FPGA_CLK  [project net DB_CLOCKS.FPGA_CLK]
FPGA_DIN: U1#4.T1(IO_L32P_3/VREF_3) ; port DB_PROGRAM.DIN  [project net DB_PROGRAM.DIN]
FPGA_DONE: U1#4.R2(IO_L30P_3) ; port DB_PROGRAM.DONE  [project net DB_PROGRAM.DONE]
FPGA_ID0: U1#4.E20(IO_L32P_1)
FPGA_ID1: U1#4.R4(IO_L33N_3)
FPGA_ID2: U1#4.F20(IO_L29P_1/A16)
FPGA_ID3: U1#4.R1(IO_L28N_3)
FPGA_INIT: U1#4.U3(IO_L34N_3) ; port DB_PROGRAM.INIT  [project net DB_PROGRAM.INIT]
FPGA_M0: U1#4.R5(IO_L36P_3)
FPGA_M1: U1#4.V2(IO_L37N_3)
FPGA_M2: U1#4.U5(IO_L05N_2)
FPGA_PROGRAM: U1#4.R7(IO_L04N_2) ; port DB_PROGRAM.PROGRAM  [project net DB_PROGRAM.PROGRAM]
FPGA_TCK: U1#4.E10(IO_L17N_0/GCLK9) ; harness JTAG.TCK
FPGA_TDI: U1#4.T6(IO_L04P_2) ; harness JTAG.TDI
FPGA_TDO: U1#4.W2(IO_L38N_3) ; harness JTAG.TDO
FPGA_TMS: U1#4.V1(IO_L37P_3) ; harness JTAG.TMS
HOST_HARD_TCK: sheet HOST_NonIO/TCK, harness JTAG.TCK
HOST_HARD_TDI: sheet HOST_NonIO/TDI, harness JTAG.TDI
HOST_HARD_TDO: sheet HOST_NonIO/TDO, harness JTAG.TDO
HOST_HARD_TMS: sheet HOST_NonIO/TMS, harness JTAG.TMS
HOST_M0: R1#3.1 U1#4.V4(IO_L01N_2/M0)
HOST_M1: J1#2.1 R2#3.1 U1#4.U4(IO_L01P_2/M1)
HOST_M2: R3#3.1 U1#4.W3(IO_L02P_2/M2)
HOST_SOFT_TCK: U1#4.D10(IO_L17P_0/GCLK8) ; harness JTAG.TCK
HOST_SOFT_TDI: U1#4.F3(IO_L09P_3) ; harness JTAG.TDI
HOST_SOFT_TDO: U1#4.F2(IO_L10N_3) ; harness JTAG.TDO
HOST_SOFT_TMS: U1#4.F7(IO_L27N_0) ; harness JTAG.TMS
HOST_VS0: R269.1 U1#4.W6(IO_L09N_2/VS0)
HOST_VS1: R270.1 U1#4.V6(IO_L09P_2/VS1)
HOST_VS2: R271.1 U1#4.U7(IO_L07N_2/VS2)
HUSB_D0: U1#4.H4(IO_L08N_3)
HUSB_D1: U1#4.F6(IO_L31N_0)
HUSB_D2: U1#4.H6(IO_L08P_3)
HUSB_D3: U1#4.G3(IO_L12P_3)
HUSB_D4: U1#4.G5(IO_L06N_3)
HUSB_D5: U1#4.G4(IO_L09N_3)
HUSB_D6: U1#4.J2(IO_L16N_3)
HUSB_D7: U1#4.H3(IO_L14N_3)
HUSB_D8: U1#4.P3(IO_L29P_3)
HUSB_D9: U1#4.M5(IO_L24N_3)
HUSB_D10: U1#4.P1(IO_L28P_3)
HUSB_D11: U1#4.M4(IO_L24P_3)
HUSB_D12: U1#4.N4(IO_L26N_3)
HUSB_D13: U1#4.M3(IO_L22N_3)
HUSB_D14: U1#4.N3(IO_L26P_3)
HUSB_D15: U1#4.M2(IO_L22P_3/VREF_3)
HUSB_FIFOADR0: U1#4.L1(IO_L21P_3/TRDY2/LHCLK6) ; port HOSTUSB.FIFOADR0  [project net HOST_USB.FIFOADR0]
HUSB_FIFOADR1: U1#4.L3(IO_L18N_3/IRDY2/LHCLK3) ; port HOSTUSB.FIFOADR1  [project net HOST_USB.FIFOADR1]
HUSB_FIFOADR2: U1#4.K3(IO_L18P_3/LHCLK2) ; port HOSTUSB.FIFOADR2  [project net HOST_USB.FIFOADR2]
HUSB_FLAGA: U1#4.G1(IO_L13N_3/VREF_3) ; port HOSTUSB.FLAGA  [project net HOST_USB.FLAGA]
HUSB_FLAGB: U1#4.J3(IO_L16P_3) ; port HOSTUSB.FLAGB  [project net HOST_USB.FLAGB]
HUSB_FLAGC: U1#4.J4(IO_L14P_3) ; port HOSTUSB.FLAGC  [project net HOST_USB.FLAGC]
HUSB_FLAGD_CS_N: U1#4.M1(IO_L21N_3/LHCLK7) ; port HOSTUSB.FLAGD_CS_N  [project net HOST_USB.FLAGD_CS_N]
HUSB_IFCLK: U1#4.H2(IO_L12N_3) ; port HOSTUSB.IFCLK  [project net HOST_USB.IFCLK]
HUSB_INT_N: U1#4.J6(IO_L07P_3) ; port HOSTUSB.INT_N  [project net HOST_USB.INT_N]
HUSB_PKTEND: U1#4.L5(IO_L20N_3/LHCLK5) ; port HOSTUSB.PKTEND  [project net HOST_USB.PKTEND]
HUSB_RD_N: U1#4.N2(IO_L25N_3) ; port HOSTUSB.RD_N  [project net HOST_USB.RD_N]
HUSB_READY: U1#4.J5(IO_L07N_3) ; port HOSTUSB.READY  [project net HOST_USB.READY]
HUSB_RESET_N: U1#4.P4(IO_L29N_3) ; port HOSTUSB.RESET_N  [project net HOST_USB.RESET_N]
HUSB_SLOE: U1#4.K2(IO_L17N_3/LHCLK1) ; port HOSTUSB.SLOE  [project net HOST_USB.SLOE]
HUSB_VBUS: U1#4.F1(IO_L13P_3) ; port HOSTUSB.VBUS  [project net HOST_USB.VBUS]
HUSB_WR_N: U1#4.K4(IO_L20P_3/LHCLK4) ; port HOSTUSB.WR_N  [project net HOST_USB.WR_N]
LED1_BLUE: U1#4.T7(IO_L06P_2) ; port LED1.BLUE  [project net HOST_LED1.BLUE]
LED1_GREEN: U1#4.Y6(IO_L10P_2) ; port LED1.GREEN  [project net HOST_LED1.GREEN]
LED1_RED: U1#4.U6(IO_L06N_2) ; port LED1.RED  [project net HOST_LED1.RED]
LED2_BLUE: U1#4.W4(IO_L03N_2) ; port LED2.BLUE  [project net HOST_LED2.BLUE]
LED2_GREEN: U1#4.Y4(IO_L08P_2) ; port LED2.GREEN  [project net HOST_LED2.GREEN]
LED2_RED: U1#4.Y5(IO_L08N_2) ; port LED2.RED  [project net HOST_LED2.RED]
NEXUS_TCK: U1#4.W9(IO_L15P_2/GCLK12) ; harness JTAG.TCK
NEXUS_TDI: U1#4.T4(IO_L36N_3) ; harness JTAG.TDI
NEXUS_TDO: U1#4.T3(IO_L33P_3) ; harness JTAG.TDO
NEXUS_TMS: U1#4.T2(IO_L32N_3) ; harness JTAG.TMS
ONE_WIRE_ID: U1#4.A14(IO_L07N_0) ; port 1WID.DATA  [project net HOST_ID.DATA]
ONE_WIRE_PB_ID_A: U1#4.V15(IO_L26N_2/D1) ; harness ONE_WIRE.ID
ONE_WIRE_PIOA1: U1#4.V16(IO_L29P_2)
ONE_WIRE_PIOA2: U1#4.U15(IO_L27P_2)
PB_SPAREA1: U1#4.V9(IO_L13N_2)
PB_SPAREA2: U1#4.T10(IO_L14N_2/D4)
PB_SPAREA3: U1#4.Y12(IO_L20P_2)
PB_SPAREA4: U1#4.U16(IO_L29N_2)
REF_CLK: U1#4.A10(IO_L16P_0/GCLK6) ; port CLK_PLL.CLK_FIXED, port DB_CLOCKS.REF_CLK  [project net DB_CLOCKS.REF_CLK]
RTC_CS: U1#4.T9(IO_L11P_2) ; port RTC.CS_N  [project net HOST_RTC.CS_N]
RTC_DIN: U1#4.V5(IO_L05P_2) ; port RTC.DIN  [project net HOST_RTC.DIN]
RTC_DOUT: U1#4.Y3(IO_L03P_2) ; port RTC.DOUT  [project net HOST_RTC.DOUT]
RTC_INT_N: U1#4.C13(IO_L10N_0/VREF_0) ; port RTC.INT_N  [project net HOST_RTC.INT_N]
RTC_SCLK: U1#4.U11(IO_L18P_2/GCLK2) ; port RTC.SCLK  [project net HOST_RTC.SCLK]
SD_CLK: U1#4.D11(IO_L15P_0/GCLK4) ; port SD.CLK  [project net HOST_SD.CLK]
SD_CMD: U1#4.U20(IO_L06N_1) ; port SD.CMD  [project net HOST_SD.CMD]
SD_DAT0: U1#4.U19(IO_L06P_1)
SD_DAT1: U1#4.V19(IO_L02P_1/LDC1)
SD_DAT2: U1#4.P20(IO_L10N_1/VREF_1)
SD_DAT3: U1#4.T20(IO_L05N_1)
SD_DETECT: U1#4.Y17(IO_L30P_2) ; port SD.DETECT  [project net HOST_SD.DETECT]
SD_PROTECT: U1#4.W20(IO_L01P_1/HDC) ; port SD.PROTECT  [project net HOST_SD.PROTECT]
SRAM_A0: U1#4.F4(IO_L06P_3)
SRAM_A1: U1#4.E1(IO_L05N_3)
SRAM_A2: U1#4.E3(IO_L10P_3)
SRAM_A3: U1#4.F8(IO_L23N_0)
SRAM_A4: U1#4.D1(IO_L05P_3)
SRAM_A5: U1#4.B1(IO_L02P_3)
SRAM_A6: U1#4.C4(IO_L29N_0)
SRAM_A7: U1#4.B2(IO_L32N_0/PUDC_B)
SRAM_A8: U1#4.C5(IO_L28P_0)
SRAM_A9: U1#4.B3(IO_L30N_0)
SRAM_A10: U1#4.A12(IO_L13N_0)
SRAM_A11: U1#4.B13(IO_L11P_0)
SRAM_A12: U1#4.B12(IO_L13P_0)
SRAM_A13: U1#4.C12(IO_L11N_0)
SRAM_A14: U1#4.B11(IO_L14P_0)
SRAM_A15: U1#4.A3(IO_L30P_0)
SRAM_A16: U1#4.D8(IO_L21N_0)
SRAM_A17: U1#4.C6(IO_L25N_0)
SRAM_A18: U1#4.C11(IO_L14N_0)
SRAM_D0: U1#4.D2(IO_L03N_3)
SRAM_D1: U1#4.D3(IO_L01N_3)
SRAM_D2: U1#4.E7(IO_L27P_0)
SRAM_D3: U1#4.D4(IO_L01P_3)
SRAM_D4: U1#4.E6(IO_L31P_0)
SRAM_D5: U1#4.C1(IO_L03P_3)
SRAM_D6: U1#4.E8(IO_L23P_0)
SRAM_D7: U1#4.C2(IO_L02N_3)
SRAM_D8: U1#4.B9(IO_L19P_0)
SRAM_D9: U1#4.A7(IO_L24N_0)
SRAM_D10: U1#4.B8(IO_L20P_0)
SRAM_D11: U1#4.A6(IO_L25P_0)
SRAM_D12: U1#4.C9(IO_L19N_0)
SRAM_D13: U1#4.B7(IO_L24P_0)
SRAM_D14: U1#4.A5(IO_L26P_0)
SRAM_D15: U1#4.C8(IO_L20N_0)
SRAM_NBHE: U1#4.C7(IO_L21P_0) ; port SRAM.NBHE  [project net HOST_SRAM.NBHE]
SRAM_NBLE: U1#4.A4(IO_L29P_0) ; port SRAM.NBLE  [project net HOST_SRAM.NBLE]
SRAM_NCS: U1#4.F9(IO_L22N_0/VREF_0) ; port SRAM.NCS  [project net HOST_SRAM.NCS]
SRAM_NOE: U1#4.B5(IO_L26N_0) ; port SRAM.NOE  [project net HOST_SRAM.NOE]
SRAM_NWE: U1#4.D6(IO_L28N_0) ; port SRAM.NWE  [project net HOST_SRAM.NWE]
USERFLASH1_CS_N: U1#4.U18(IO_L02N_1/LDC0) ; port FLASH_USER.FLASH1_CS_N  [project net USER_FLASH.FLASH1_CS_N]
USERFLASH2_CS_N: U1#4.T12(IO_L19P_2) ; port FLASH_USER.FLASH2_CS_N  [project net USER_FLASH.FLASH2_CS_N]
USERFLASH_DIN: U1#4.T15(IO_L27N_2) ; port FLASH_USER.DIN  [project net USER_FLASH.DIN]
USERFLASH_DOUT: U1#4.T14(IO_L25N_2) ; port FLASH_USER.DOUT  [project net USER_FLASH.DOUT]
USERFLASH_SCLK: U1#4.T13(IO_L23P_2) ; port FLASH_USER.SCLK  [project net USER_FLASH.SCLK]

Not connected (* = marked no-connect by the designer): U1#4 A15(IO_L08N_0)* A16(IO_L05N_0)* A17(IO_L04N_0)* A18(IO_L01N_0)* B15(IO_L08P_0)* B17(IO_L04P_0/VREF_0)* B18(IO_L01P_0)* B19(IO_L38N_1/A25)* B20(IO_L38P_1/A24)* C14(IO_L07P_0)* C15(IO_L06N_0)* C16(IO_L05P_0)* C17(IO_L02N_0)* C19(IO_L37N_1/A23)* C20(IO_L37P_1/A22)* D12(IO_L12P_0)* D14(IO_L10P_0)* D15(IO_L06P_0)* D16(IO_L03P_0)* D17(IO_L02P_0/VREF_0)* D18(IO_L34N_1)* D20(IO_L34P_1)* E13(IO_L09P_0)* E14(IP_0)* E15(IO_L03N_0)* E18(IO_L33P_1)* E19(IO_L32N_1)* F11(IP_0)* F12(IO_L12N_0)* F13(IO_L09N_0)* F14(IP_0)* F16(IO_L36N_1/A21)* F17(IO_L33N_1)* F18(IO_L30N_1/A19)* F19(IO_L29N_1/A17)* G6(IP_L04N_3/VREF_3)* G7(IP_L04P_3)* G8(IP_0)* G9(IP_0)* G10(IP_0)* G11(IP_0/VREF_0)* G12(IP_0)* G13(IP_0)* G14(IP_L39N_1)* G15(IP_L39P_1/VREF_1)* G16(IO_L36P_1/A20)* G17(IO_L30P_1/A18)* G18(IO_L28P_1)* G20(IO_L26N_1/A15)* H7(IP_3)* H9(IP_0)* H10(IP_0)* H11(IP_0)* H12(IP_0)* H14(IP_L35N_1)* H15(IP_L35P_1)* H17(IO_L28N_1)* H18(IO_L25N_1/A13)* H19(IO_L25P_1/A12)* H20(IO_L26P_1/A14)* J7(IP_L11N_3/VREF_3)* J8(IP_L11P_3)* J13(IP_L31N_1)* J14(IP_L31P_1/VREF_1)* J15(IP_L27N_1)* J16(IP_L27P_1)* J17(IO_L24P_1)* J18(IO_L22N_1/A11)* J19(IO_L22P_1/A10)* J20(IO_L21N_1/RHCLK7)* K5(IP_L19N_3)* K6(IP_L19P_3)* K7(IP_L15N_3)* K8(IP_L15P_3)* K14(IP_L23N_1)* K15(IP_L23P_1/VREF_1)* K16(IO_L24N_1)* K18(IO_L20P_1/RHCLK4)* K20(IO_L21P_1/IRDY1/RHCLK6)* L6(IP_L23N_3)* L7(IP_L23P_3)* L13(IP_L19N_1)* L14(IP_L19P_1)* L15(IO_L16P_1/A8)* L16(IO_L16N_1/A9)* L17(IO_L20N_1/RHCLK5)* L18(IO_L18N_1/TRDY1/RHCLK3)* L19(IO_L18P_1/RHCLK2)* M6(IP_L31P_3)* M7(IP_L27N_3)* M8(IP_L27P_3)* M13(IP_L15N_1)* M14(IP_L15P_1/VREF_1)* M15(IP_L11N_1/VREF_1)* M16(IP_L11P_1)* M17(IO_L14P_1/A6)* M18(IO_L14N_1/A7)* M19(IO_L17P_1/RHCLK0)* M20(IO_L17N_1/RHCLK1)* N6(IP_L35N_3)* N7(IP_L31N_3)* N9(IP_2/VREF_2)* N12(IP_2/VREF_2)* N14(IP_1/VREF_1)* N15(IO_L12P_1/A2)* N17(IO_L12N_1/A3)* N18(IO_L13P_1/A4)* N19(IO_L13N_1/A5)* P5(IP_L35P_3)* P6(IP_L39P_3)* P7(IP_L39N_3/VREF_3)* P8(IP_2/VREF_2)* P9(IP_2)* P10(IP_2/VREF_2)* P11(IP_2/VREF_2)* P12(IP_2)* P13(IP_2)* P14(IP_L04P_1)* P15(IP_L04N_1/VREF_1)* P16(IO_L07P_1)* P17(IO_L07N_1)* P18(IO_L10P_1)* R8(IP_2)* R10(IP_2)* R14(IP_2/VREF_2)* R16(IO_L03N_1/A1)* R17(IO_L08N_1)* R18(IO_L08P_1)* R19(IO_L09P_1)* R20(IO_L09N_1)* T11(IP_2)* T18(IO_L05P_1)*

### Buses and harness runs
bus CLK_EXTA[2..0]
bus EXTSPI_CSA_N[1..0]
bus FPGA_ID[3..0]
bus FPGA_M[2..0]
bus HUSB_D[15..0]
bus ONE_WIRE_PIOA[1..2]
bus PB_SPAREA[1..4]
bus SD_DAT[3..0]
bus SRAM_A[18..0]
bus SRAM_D[15..0]

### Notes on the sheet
- SYSTEM CLOCKS
- HOST RTC
- USER FPGA JTAG
- HOST USB
- PB - Control
- SRAM - 64K/256K x 16
- ONE WIRE ID
- USER FPGA PROGRAM
- USB2
- USER 8MB SPI FLASH x2
- HOST AUDIO - Delta-Sigma
- SYSBOOT
- PB SPI
- HOST JTAG
- USER FPGA SPI
- HOST SD CARD
- Host LEDs
- GOLDEN
- (near J1#2) PLATFORM UPGRADE
- HSWAP
- HSWAP HIGH = INT PULLUPS OFF
- (INT PULLED UP VIA FIXED RESISTOR)
- HSWAP LOW= INT PULLUPS ON
- XC3S1400AN MODE PIN CONFIGURATIONS
- M2  M1  M0
- FUNCTION:
- 0
- 1
- PLATFORM FLASH MODE
- SPI MODE (MASTER)
- BYTE PARALLED INTERFACE
- INTERNAL MASTER SPI FLASH
- <RESERVED>
- JTAG MODE
- SLAVE PARALLEL
- SLAVE SERIAL
- M0
- START ADD = 0x00_0000 INCREMENTING
- (INT PULL UP VIA HSWAP)
- START ADD = 0xFF_FFFF DECREMENTING
- M1
- MUST BE PULLED HIGH DURING CONFIG
- M2
- MUST BE PULLED LOW DURING CONFIG
- XC3S1400AN SPI MODE CONFIGURATIONS
- VS2 VS1 VS0
- 1V2
- (0x03) STANDARD READ
- (0xE8) READ ARRAY
- (0x0B) SPI FAST READ
- 3V3
- VS0
- SPI SET TO FAST (0x0B)
- SPI ACCESS SPEED (INT PULL UP VIA HSWAP)
- VCCO_2
- VS1
- VS2
- PROG_B
- DONE

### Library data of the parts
J1#2 = D-300-0020: Header IDC, 2 x 1 Pin Vertical 2.54mm Pitch (Non-Boxed, Male); Max Current: 3 A
R1#3 R2#3 R3#3 R99 R269-R271 = D-100-0107: Resistor, 2K2 1% 0402 (1005); Power Rating: 63 mW; Resistance: 2.2 K
R1_HOST = D-100-0085: Resistor, 5R6 1% 0402 (1005); Power Rating: 63 mW; Resistance: 5.6 R
U1#4 = D-241-0024: FPGA, Xilinx Spartan3-400 Standard Speed, BGA 1.0mm pitch, 400 balls, 0 to 85 degC; Supply Voltage: 1.2, 2.5, and 3.3 V

## Sheet HOST_FPGA_NonIO.SchDoc: HOST FPGA Pwr and Programming
size A4; Organization: Altium Limited.; Address1: Level 3, 12a Rodborough Rd; Address2: Frenchs Forest 2086; Address3: NSW; Address4: AUSTRALIA; DocumentNumber: 22; SheetNumber: 23; SheetTotal: 78
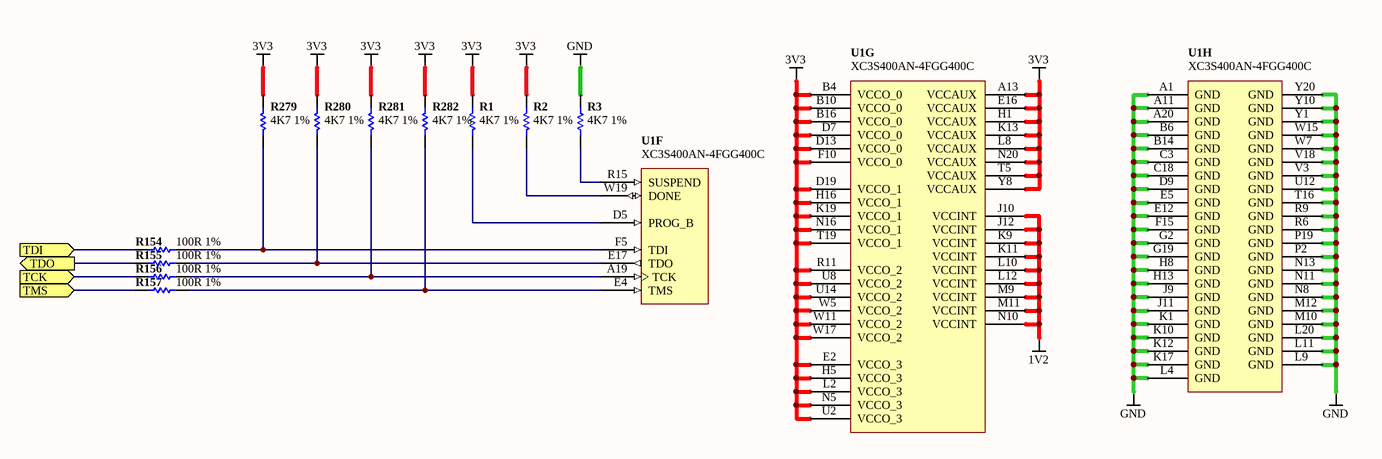
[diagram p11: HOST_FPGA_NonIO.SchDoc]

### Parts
(Parts that share a designator on the sheet are numbered #1, #2 ... from top to bottom, then left to right.)
R1#4  4K7 1%  [RESC1005-STAR]
R2#4  4K7 1%  [RESC1005-STAR]
R3#4  4K7 1%  [RESC1005-STAR]
R154#1  100R 1%  [RESC1005-STAR]
R155  100R 1%  [RESC1005-STAR]
R156  100R 1%  [RESC1005-STAR]
R157  100R 1%  [RESC1005-STAR]
R279  4K7 1%  [RESC1005-STAR]
R280  4K7 1%  [RESC1005-STAR]
R281  4K7 1%  [RESC1005-STAR]
R282  4K7 1%  [RESC1005-STAR]
U1#4  XC3S400AN-4FGG400C  [FGG400]  (parts F,G,H of 8)

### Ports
TCK (in), TDI (in), TDO (out), TMS (in)

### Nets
1V2: U1#4.J10(VCCINT) U1#4.J12(VCCINT) U1#4.K9(VCCINT) U1#4.K11(VCCINT) U1#4.L10(VCCINT) U1#4.L12(VCCINT) U1#4.M9(VCCINT) U1#4.M11(VCCINT) U1#4.N10(VCCINT)
3V3: R1#4.1 R2#4.1 R279.1 R280.1 R281.1 R282.1 U1#4.A13(VCCAUX) U1#4.B4(VCCO_0) U1#4.B10(VCCO_0) U1#4.B16(VCCO_0) U1#4.D7(VCCO_0) U1#4.D13(VCCO_0) U1#4.D19(VCCO_1) U1#4.E2(VCCO_3) U1#4.E16(VCCAUX) U1#4.F10(VCCO_0) U1#4.H1(VCCAUX) U1#4.H5(VCCO_3) U1#4.H16(VCCO_1) U1#4.K13(VCCAUX) U1#4.K19(VCCO_1) U1#4.L2(VCCO_3) U1#4.L8(VCCAUX) U1#4.N5(VCCO_3) U1#4.N16(VCCO_1) U1#4.N20(VCCAUX) U1#4.R11(VCCO_2) U1#4.T5(VCCAUX) U1#4.T19(VCCO_1) U1#4.U2(VCCO_3) U1#4.U8(VCCO_2) U1#4.U14(VCCO_2) U1#4.W5(VCCO_2) U1#4.W11(VCCO_2) U1#4.W17(VCCO_2) U1#4.Y8(VCCAUX)
GND: R3#4.1 U1#4.A1(GND) U1#4.A11(GND) U1#4.A20(GND) U1#4.B6(GND) U1#4.B14(GND) U1#4.C3(GND) U1#4.C18(GND) U1#4.D9(GND) U1#4.E5(GND) U1#4.E12(GND) U1#4.F15(GND) U1#4.G2(GND) U1#4.G19(GND) U1#4.H8(GND) U1#4.H13(GND) U1#4.J9(GND) U1#4.J11(GND) U1#4.K1(GND) U1#4.K10(GND) U1#4.K12(GND) U1#4.K17(GND) U1#4.L4(GND) U1#4.L9(GND) U1#4.L11(GND) U1#4.L20(GND) U1#4.M10(GND) U1#4.M12(GND) U1#4.N8(GND) U1#4.N11(GND) U1#4.N13(GND) U1#4.P2(GND) U1#4.P19(GND) U1#4.R6(GND) U1#4.R9(GND) U1#4.T16(GND) U1#4.U12(GND) U1#4.V3(GND) U1#4.V18(GND) U1#4.W7(GND) U1#4.W15(GND) U1#4.Y1(GND) U1#4.Y10(GND) U1#4.Y20(GND)
HOST_HARD_TCK: R156.1 ; port TCK
HOST_HARD_TDI: R154#1.1 ; port TDI
HOST_HARD_TDO: R155.1 ; port TDO
HOST_HARD_TMS: R157.1 ; port TMS
NetR1#4_2: R1#4.2 U1#4.D5(PROG_B)
NetR2#4_2: R2#4.2 U1#4.W19(DONE)
NetR3#4_2: R3#4.2 U1#4.R15(SUSPEND)
NetR154#1_2: R154#1.2 R279.2 U1#4.F5(TDI)
NetR155_2: R155.2 R280.2 U1#4.E17(TDO)
NetR156_2: R156.2 R281.2 U1#4.A19(TCK)
NetR157_2: R157.2 R282.2 U1#4.E4(TMS)

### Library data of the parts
R1#4 R2#4 R3#4 R279-R282 = D-100-0088: Resistor, 4K7 1% 0402 (1005); Power Rating: 63 mW; Resistance: 4.7 K
R154#1 R155-R157 = D-100-0131: Resistor, 100R 1% 0402 (1005); Power Rating: 63 mW
U1#4 = D-241-0024: as U1#4 on sheet Host_FPGA

## Sheet HOST_JTAG.SchDoc: Local MCU Debug Connector
size A4; DocumentNumber: 24; SheetNumber: 25; SheetTotal: 78
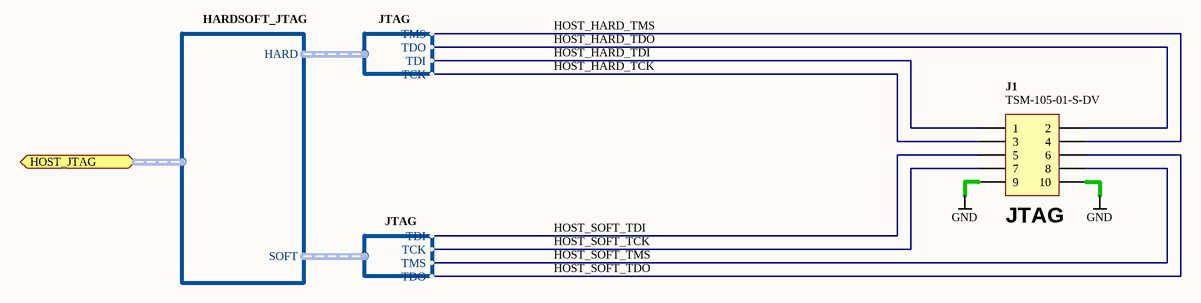
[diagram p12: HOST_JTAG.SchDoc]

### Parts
(Parts that share a designator on the sheet are numbered #1, #2 ... from top to bottom, then left to right.)
J1#3  TSM-105-01-S-DV  [TSM-105-01-DV]

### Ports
HOST_JTAG (harness HARDSOFT_JTAG)

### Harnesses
JTAG: TMS, TDO, TDI, TCK
HARDSOFT_JTAG: HARD, SOFT

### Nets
GND: J1#3.9 J1#3.10
HOST_HARD_TCK: J1#3.3 ; harness JTAG.TCK
HOST_HARD_TDI: J1#3.1 ; harness JTAG.TDI
HOST_HARD_TDO: J1#3.2 ; harness JTAG.TDO
HOST_HARD_TMS: J1#3.4 ; harness JTAG.TMS
HOST_SOFT_TCK: J1#3.7 ; harness JTAG.TCK
HOST_SOFT_TDI: J1#3.5 ; harness JTAG.TDI
HOST_SOFT_TDO: J1#3.6 ; harness JTAG.TDO
HOST_SOFT_TMS: J1#3.8 ; harness JTAG.TMS

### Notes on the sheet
- (near J1#3) JTAG

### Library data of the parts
J1#3 = D-300-0076: Non-Boxed Header IDC, 2 X 5 Pin SMD; Connector type: Boxed; Max Current: mA

## Sheet USB_CY7C68001-56LFC.SchDoc: High-Speed USB 2.0 Controller
size A4; Organization: Altium Limited.; Address1: Level 3, 12a Rodborough Rd; Address2: Frenchs Forest 2086; Address3: NSW; Address4: AUSTRALIA; DocumentNumber: 49; SheetNumber: 50; SheetTotal: 78
Used 2 times, as channels DBUSB_TXRX, DBUSB_TXRX. Parts and nets are listed once, with the designators drawn on the sheet.
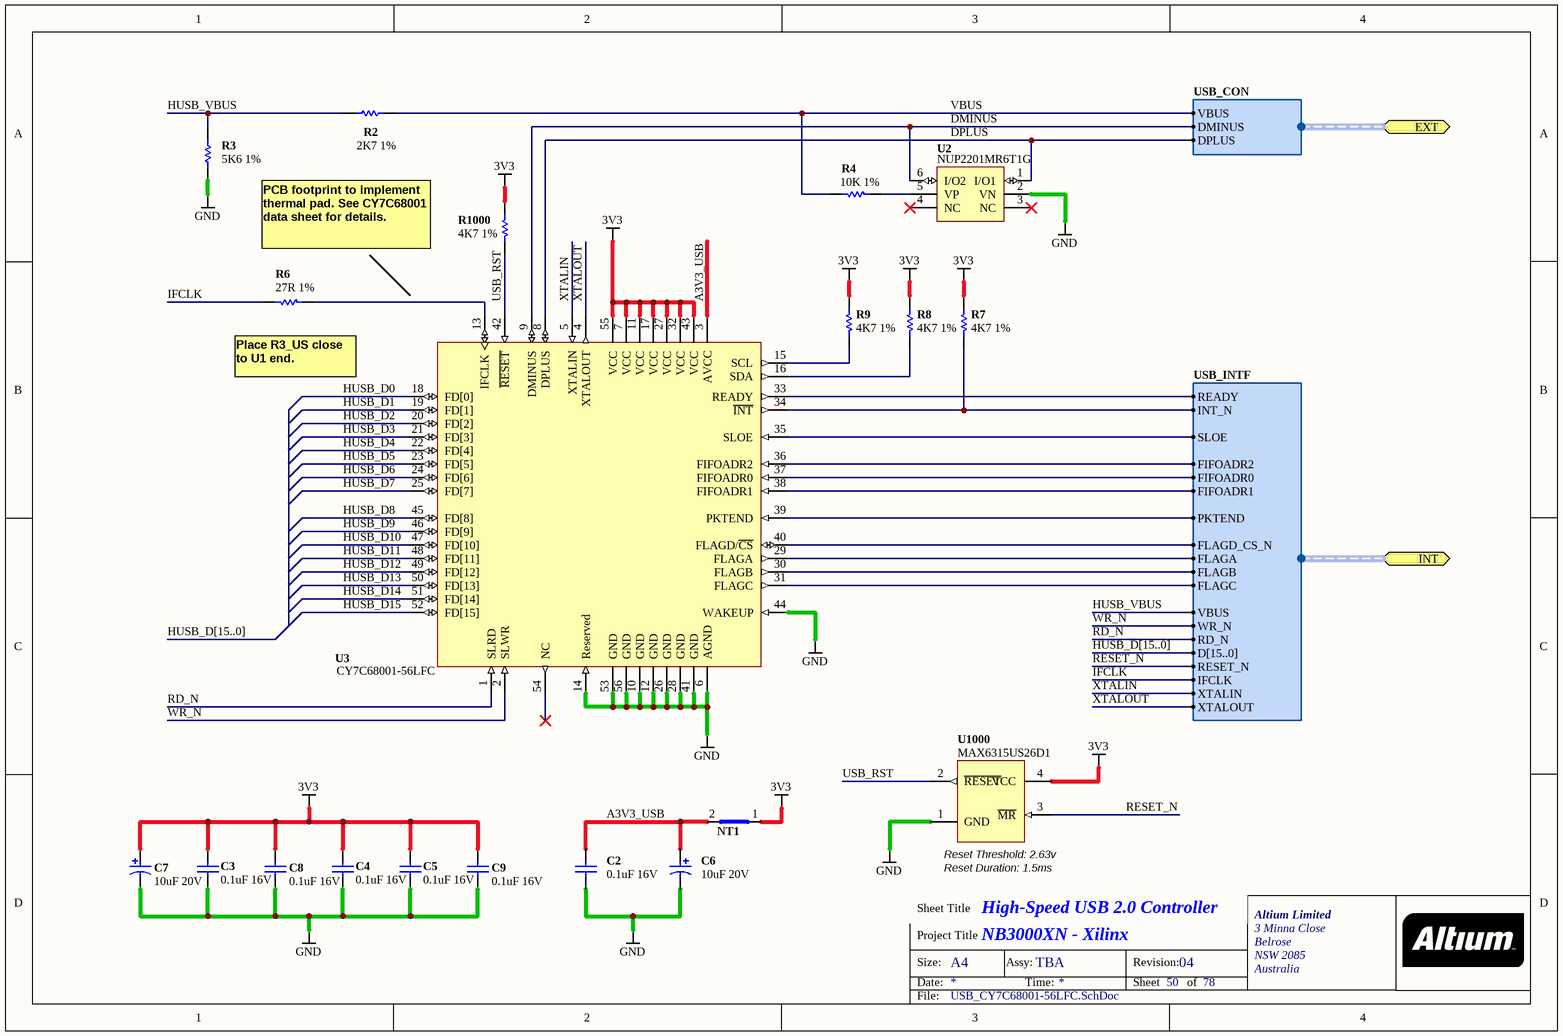
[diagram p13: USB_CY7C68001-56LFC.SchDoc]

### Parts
C2  0.1uF 16V  [CAPC1005-STAR]
C3  0.1uF 16V  [CAPC1005-STAR]
C4  0.1uF 16V  [CAPC1005-STAR]
C5  0.1uF 16V  [CAPC1005-STAR]
C6  10uF 20V  [CAPC3528-STAR]
C7  10uF 20V  [CAPC3528-STAR]
C8  0.1uF 16V  [CAPC1005-STAR]
C9  0.1uF 16V  [CAPC1005-STAR]
NT1  Net Tie SMT2  [NETTIE-SMT2-31X51]  (value not drawn)  (net tie, no BOM)
R2  2K7 1%  [RESC1005-STAR]
R3  5K6 1%  [RESC1005-STAR]
R4  10K 1%  [RESC1005-STAR]
R6  27R 1%  [RESC1005-STAR]
R7  4K7 1%  [RESC1005-STAR]
R8  4K7 1%  [RESC1005-STAR]
R9  4K7 1%  [RESC1005-STAR]
R1000  4K7 1%  [RESC1005-STAR]
U2  NUP2201MR6T1G  [TSOP95P275-6]
U3  CY7C68001-56LFC  [QFN50P800X800_HS-57]
U1000  MAX6315US26D1  [SOT143]

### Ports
EXT (harness USB_CON), INT (harness USB_INTF)

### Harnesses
USB_INTF: READY, INT_N, SLOE, FIFOADR2, FIFOADR0, FIFOADR1, PKTEND, FLAGD_CS_N, FLAGA, FLAGB, FLAGC, WR_N, RD_N, D[15..0], RESET_N, IFCLK, XTALIN, VBUS, XTALOUT
USB_CON: VBUS, DMINUS, DPLUS

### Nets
3V3: C3.2 C4.2 C5.2 C7.1 C8.1 C9.1 NT1.1(Net1) R7.2 R8.1 R9.1 R1000.2 U3.7(VCC) U3.11(VCC) U3.17(VCC) U3.27(VCC) U3.32(VCC) U3.43(VCC) U3.55(VCC) U1000.4(VCC)
GND: C2.1 C3.1 C4.1 C5.1 C6.2 C7.2 C8.2 C9.2 R3.2 U2.2(VN) U3.6(AGND) U3.10(GND) U3.12(GND) U3.14(Reserved) U3.26(GND) U3.28(GND) U3.41(GND) U3.44(WAKEUP) U3.53(GND) U3.56(GND) U1000.1(GND)
A3V3_USB: C2.2 C6.1 NT1.2(Net2) U3.3(AVCC)
DMINUS: U2.6(I/O2) U3.9(DMINUS) ; port EXT.DMINUS
DPLUS: U2.1(I/O1) U3.8(DPLUS) ; port EXT.DPLUS
HUSB_D0: U3.18(FD[0])
HUSB_D1: U3.19(FD[1])
HUSB_D2: U3.20(FD[2])
HUSB_D3: U3.21(FD[3])
HUSB_D4: U3.22(FD[4])
HUSB_D5: U3.23(FD[5])
HUSB_D6: U3.24(FD[6])
HUSB_D7: U3.25(FD[7])
HUSB_D8: U3.45(FD[8])
HUSB_D9: U3.46(FD[9])
HUSB_D10: U3.47(FD[10])
HUSB_D11: U3.48(FD[11])
HUSB_D12: U3.49(FD[12])
HUSB_D13: U3.50(FD[13])
HUSB_D14: U3.51(FD[14])
HUSB_D15: U3.52(FD[15])
HUSB_VBUS: R2.1 R3.1 ; port INT.VBUS
IFCLK: R6.1 ; port INT.IFCLK
RD_N: U3.1(SLRD) ; port INT.RD_N
RESET_N: U1000.3(~{MR}) ; port INT.RESET_N
USB_RST: R1000.1 U3.42(~{RESET}) U1000.2(~{RESET})
VBUS: R2.2 R4.1 ; port EXT.VBUS
WR_N: U3.2(SLWR) ; port INT.WR_N
XTALIN: U3.5(XTALIN) ; port INT.XTALIN
XTALOUT: U3.4(XTALOUT) ; port INT.XTALOUT
NetR4_2: R4.2 U2.5(VP)
NetR6_2: R6.2 U3.13(IFCLK)
NetR7_1: R7.1 U3.34(~{INT}) ; port INT.INT_N
NetR8_2: R8.2 U3.16(SDA)
NetR9_2: R9.2 U3.15(SCL)
NetU3_29: U3.29(FLAGA) ; port INT.FLAGA
NetU3_30: U3.30(FLAGB) ; port INT.FLAGB
NetU3_31: U3.31(FLAGC) ; port INT.FLAGC
NetU3_33: U3.33(READY) ; port INT.READY
NetU3_35: U3.35(SLOE) ; port INT.SLOE
NetU3_36: U3.36(FIFOADR2) ; port INT.FIFOADR2
NetU3_37: U3.37(FIFOADR0) ; port INT.FIFOADR0
NetU3_38: U3.38(FIFOADR1) ; port INT.FIFOADR1
NetU3_39: U3.39(PKTEND) ; port INT.PKTEND
NetU3_40: U3.40(FLAGD/~{CS}) ; port INT.FLAGD_CS_N

Not connected (* = marked no-connect by the designer): U2 3(NC)* 4(NC)*; U3 54(NC)*

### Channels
DBUSB_TXRX: designators end in A
DBUSB_TXRX: designators end in B

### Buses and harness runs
bus HUSB_D[15..0]

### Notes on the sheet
- PCB footprint to implement thermal pad. See CY7C68001 data sheet for details.
- (near R6) Place R3_US close to U1 end.
- (near U1000) Reset Threshold: 2.63v
- (near U1000) Reset Duration: 1.5ms

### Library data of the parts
C2-C5 C8 C9 = D-101-0080: as C5_FP on sheet FPGA_Bypass_1V2
C6 C7 = D-101-0007: as C1_FP on sheet FPGA_Bypass_1V2
NT1 = D-002-0003: Net-Tie, Surface Mount, 2 x 1.6mm x 0.8mm SMT Pads - For 0.8mm Track
R2 = D-100-0105: Resistor, 2K7 1% 0402 (1005); Power Rating: 63 mW; Resistance: 2.7 K
R3 = D-100-0086: Resistor, 5K6 1% 0402 (1005); Power Rating: 63 mW; Resistance: 5.6 K
R4 = D-100-0130: Resistor, 10K 1% 0402 (1005); Power Rating: 63 mW
R6 = D-100-0108: Resistor, 27R 1% 0402 (1005); Power Rating: 63 mW
R7-R9 R1000 = D-100-0088: as R1#4 on sheet HOST_FPGA_NonIO
U2 = D-204-0001: NUP2201MR6, Low Capacitance Diode Array, USB Protection; Max Input Voltage: mV; Max Output Current: mA
U3 = D-221-0004: CY7C68001-56LFC, EZ-USB SX2 High-Speed USB Interface; Comm Standard: None
U1000 = D-243-0000: MAX6315, Open-Drain Output SOT Reset IC, Customized Reset Thresholds, Timeout Delays

## Sheet Ethernet_RTL8201CL.SchDoc: Ethernet Interface
size A3; DocumentNumber: 21; SheetNumber: 22; SheetTotal: 78; Organization: Altium Limited.; Address1: Level 3, 12a Rodborough Rd; Address2: Frenchs Forest 2086; Address3: NSW; Address4: AUSTRALIA
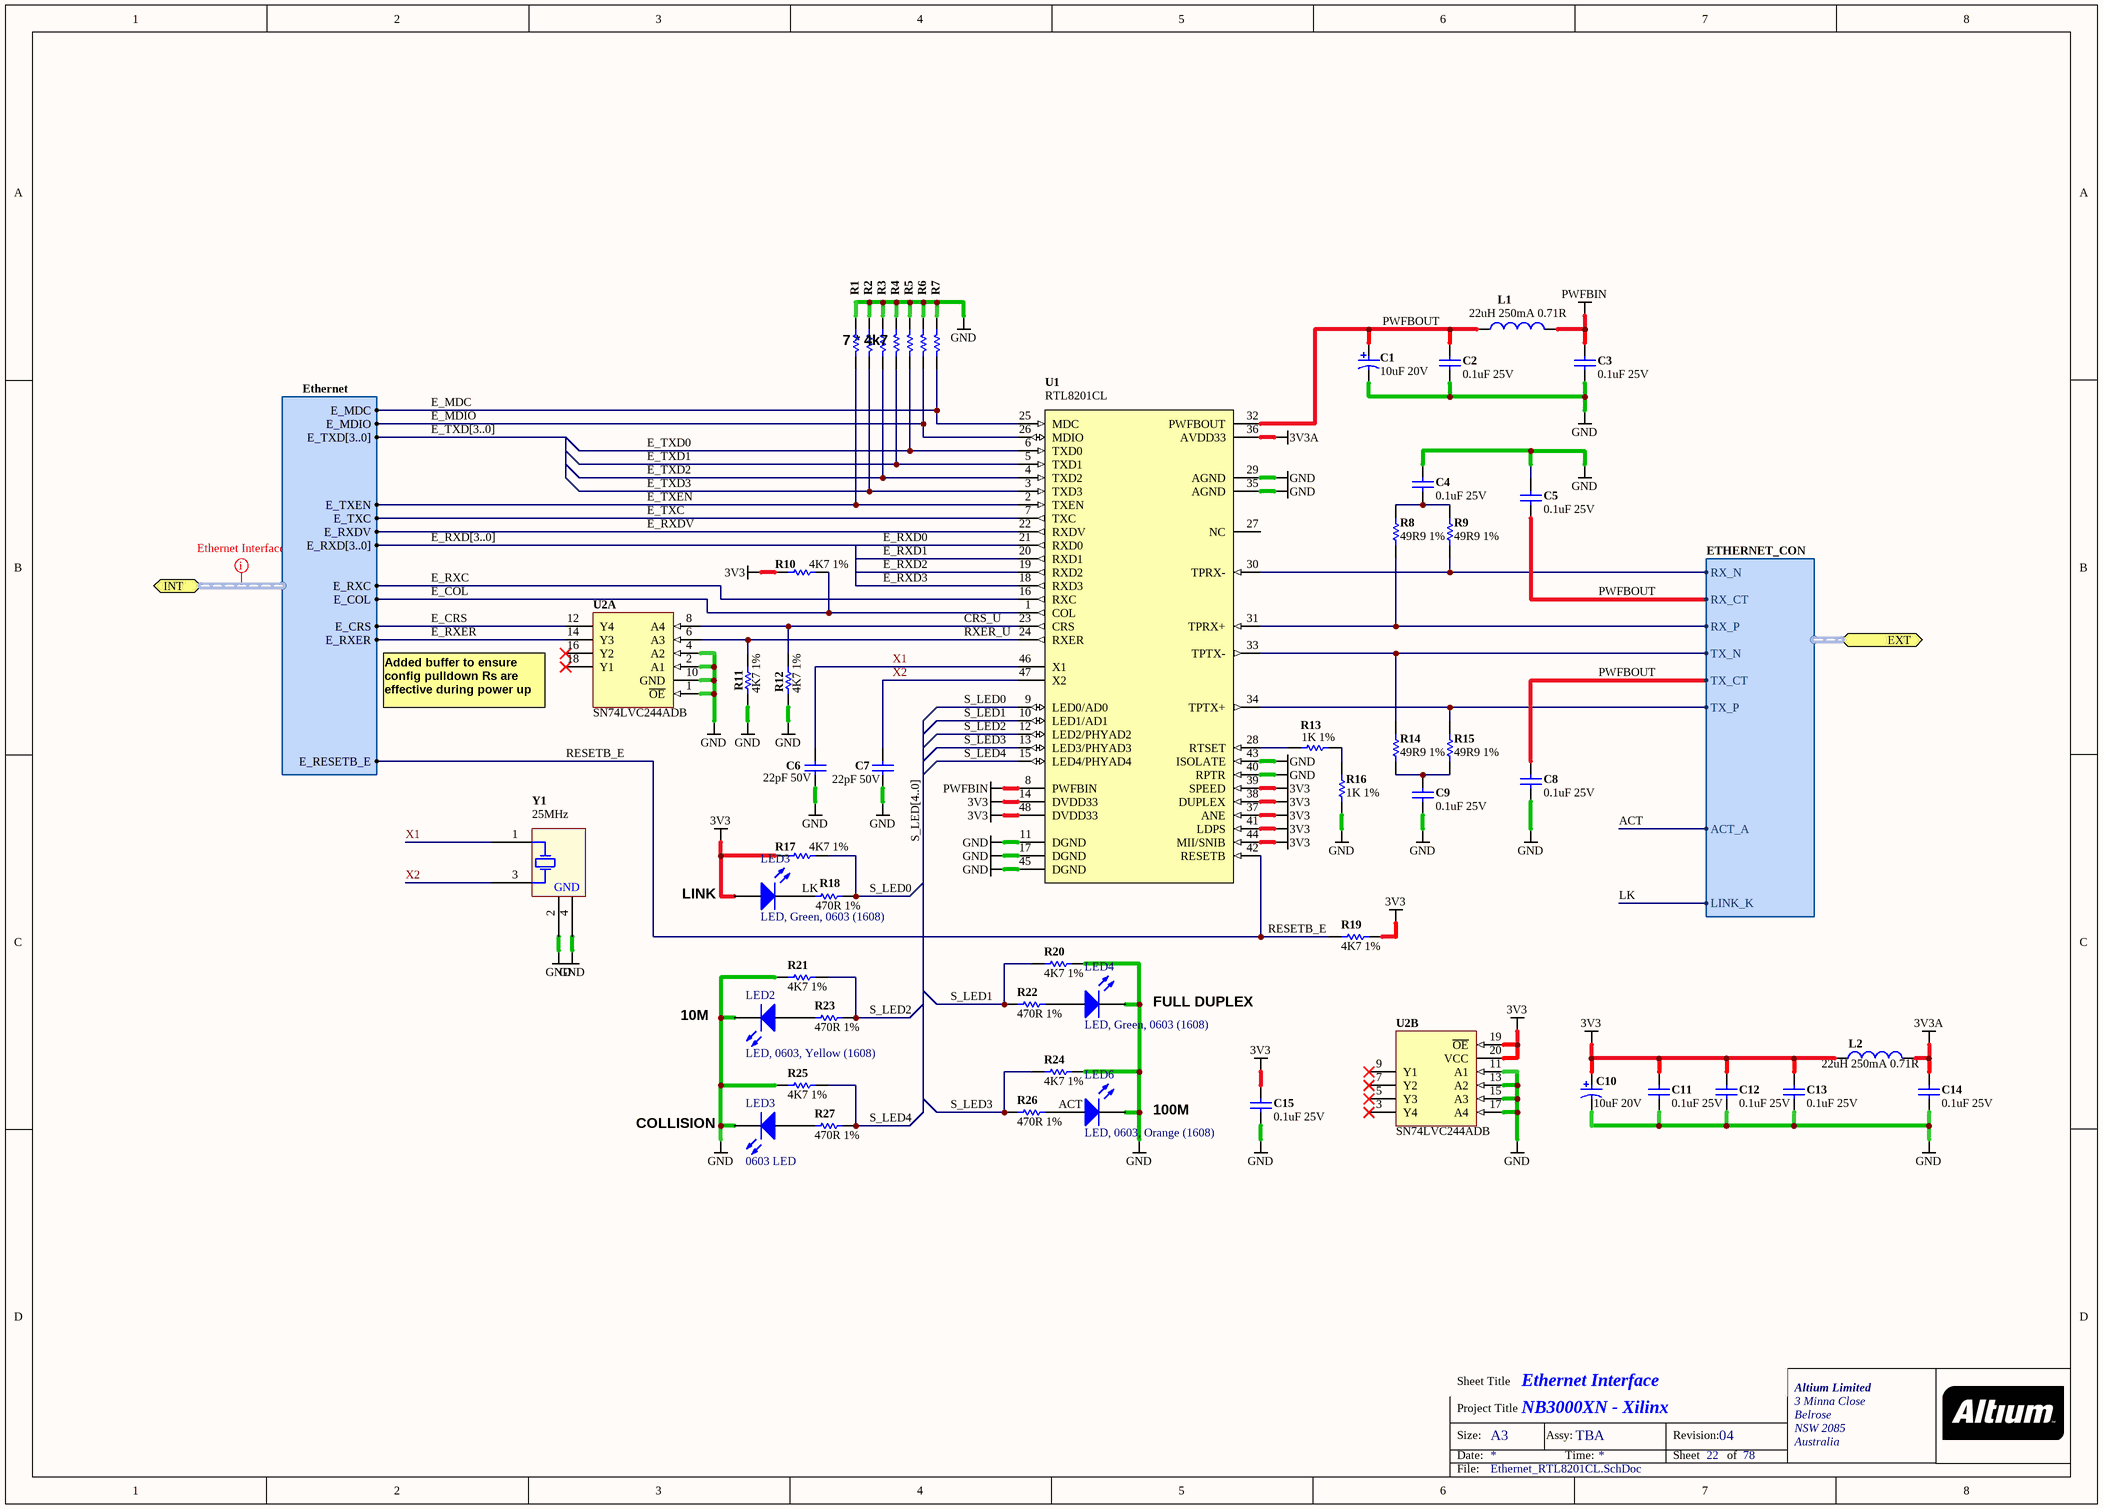
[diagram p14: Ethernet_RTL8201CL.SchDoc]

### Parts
(Parts that share a designator on the sheet are numbered #1, #2 ... from top to bottom, then left to right.)
C1#3  10uF 20V  [CAPC3528-STAR]
C2#3  0.1uF 25V  [CAPC1005-STAR]
C3#3  0.1uF 25V  [CAPC1005-STAR]
C4#3  0.1uF 25V  [CAPC1005-STAR]
C5#2  0.1uF 25V  [CAPC1005-STAR]
C6  22pF 50V  [CAPC1005-STAR]
C7  22pF 50V  [CAPC1005-STAR]
C8  0.1uF 25V  [CAPC1005-STAR]
C9  0.1uF 25V  [CAPC1005-STAR]
C10  10uF 20V  [CAPC3528-STAR]
C11  0.1uF 25V  [CAPC1005-STAR]
C12  0.1uF 25V  [CAPC1005-STAR]
C13  0.1uF 25V  [CAPC1005-STAR]
C14  0.1uF 25V  [CAPC1005-STAR]
C15  0.1uF 25V  [CAPC1005-STAR]
L1#2  22uH 250mA 0.71R  [INDC3225]
L2  22uH 250mA 0.71R  [INDC3225]
LED2  LED, 0603, Yellow (1608)  [0603LED_YELLOW]
LED3#1  LED, Green, 0603 (1608)  [0603LED_GREEN]
LED3#2  0603 LED  [0603LED_RED]
LED4  LED, Green, 0603 (1608)  [0603LED_GREEN]
LED6  LED, 0603, Orange (1608)  [0603LED_ORANGE]
R1#5  4K7 1%  [RESC1005-STAR]  (value not drawn)
R2#5  4K7 1%  [RESC1005-STAR]  (value not drawn)
R3#5  4K7 1%  [RESC1005-STAR]  (value not drawn)
R4#3  4K7 1%  [RESC1005-STAR]  (value not drawn)
R5#2  4K7 1%  [RESC1005-STAR]  (value not drawn)
R6#2  4K7 1%  [RESC1005-STAR]  (value not drawn)
R7#2  4K7 1%  [RESC1005-STAR]  (value not drawn)
R8#2  49R9 1%  [RESC2012-STAR]
R9#2  49R9 1%  [RESC2012-STAR]
R10#2  4K7 1%  [RESC1005-STAR]
R11  4K7 1%  [RESC1005-STAR]
R12#2  4K7 1%  [RESC1005-STAR]
R13  1K 1%  [RESC1005-STAR]
R14#2  49R9 1%  [RESC2012-STAR]
R15  49R9 1%  [RESC2012-STAR]
R16  1K 1%  [RESC1005-STAR]
R17  4K7 1%  [RESC1005-STAR]
R18#2  470R 1%  [RESC1005-STAR]
R19  4K7 1%  [RESC1005-STAR]
R20#2  4K7 1%  [RESC1005-STAR]
R21  4K7 1%  [RESC1005-STAR]
R22#2  470R 1%  [RESC1005-STAR]
R23#2  470R 1%  [RESC1005-STAR]
R24#2  4K7 1%  [RESC1005-STAR]
R25  4K7 1%  [RESC1005-STAR]
R26  470R 1%  [RESC1005-STAR]
R27  470R 1%  [RESC1005-STAR]
U1#5  RTL8201CL  [TSQFP50P900X900-48]
U2  SN74LVC244ADB  [SOP65P780-20]  (parts A,B of 2)
Y1#1  25MHz  [XTAL-200X126-4]

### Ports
EXT (harness ETHERNET_CON), INT (harness Ethernet)

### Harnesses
Ethernet: E_MDC, E_MDIO, E_TXD[3..0], E_TXC, E_TXEN, E_RXDV, E_RXD[3..0], E_RESETB_E, E_RXC, E_COL, E_CRS, E_RXER
ETHERNET_CON: TX_P, TX_N, RX_P, RX_N, RX_CT, TX_CT, LINK_K, ACT_A

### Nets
3V3: C10.1 C11.2 C12.2 C13.2 C15.2 L2.1 LED3#1.1(A) R10#2.2 R17.2 R19.2 U1#5.14(DVDD33) U1#5.37(ANE) U1#5.38(DUPLEX) U1#5.39(SPEED) U1#5.41(LDPS) U1#5.44(MII/SNIB) U1#5.48(DVDD33) U2.19(~{OE}) U2.20(VCC)
3V3A: C14.2 L2.2 U1#5.36(AVDD33)
GND: C1#3.2 C2#3.1 C3#3.1 C4#3.2 C5#2.2 C6.1 C7.1 C8.1 C9.1 C10.2 C11.1 C12.1 C13.1 C14.1 C15.1 LED2.2(K) LED3#2.2(K) LED4.2(K) LED6.2(K) R1#5.2 R2#5.2 R3#5.2 R4#3.2 R5#2.2 R6#2.2 R7#2.2 R11.2 R12#2.2 R16.1 R20#2.1 R21.2 R24#2.1 R25.2 U1#5.11(DGND) U1#5.17(DGND) U1#5.29(AGND) U1#5.35(AGND) U1#5.40(RPTR) U1#5.43(ISOLATE) U1#5.45(DGND) U2.1(~{OE}) U2.2(A1) U2.4(A2) U2.10(GND) U2.11(A1) U2.13(A2) U2.15(A3) U2.17(A4) Y1#1.2(GND) Y1#1.4(GND)
PWFBIN: C3#3.2 L1#2.2 U1#5.8(PWFBIN)
ACT: LED6.1(A) R26.2 ; port EXT.ACT_A  [project net ETH#.ACT_A]
CRS_U: R12#2.1 U1#5.23(CRS) U2.8(A4)
E_COL: R10#2.1 U1#5.1(COL) ; port INT.E_COL  [project net ETH.E_COL]
E_CRS: U2.12(Y4) ; port INT.E_CRS  [project net ETH.E_CRS]
E_MDC: R7#2.1 U1#5.25(MDC) ; port INT.E_MDC  [project net ETH.E_MDC]
E_MDIO: R6#2.1 U1#5.26(MDIO) ; port INT.E_MDIO  [project net ETH.E_MDIO]
E_RXC: U1#5.16(RXC) ; port INT.E_RXC  [project net ETH.E_RXC]
E_RXD0: U1#5.21(RXD0)
E_RXD1: U1#5.20(RXD1)
E_RXD2: U1#5.19(RXD2)
E_RXD3: U1#5.18(RXD3)
E_RXDV: U1#5.22(RXDV) ; port INT.E_RXDV  [project net ETH.E_RXDV]
E_RXER: U2.14(Y3) ; port INT.E_RXER  [project net ETH.E_RXER]
E_TXC: U1#5.7(TXC) ; port INT.E_TXC  [project net ETH.E_TXC]
E_TXD0: R5#2.1 U1#5.6(TXD0)
E_TXD1: R4#3.1 U1#5.5(TXD1)
E_TXD2: R3#5.1 U1#5.4(TXD2)
E_TXD3: R2#5.1 U1#5.3(TXD3)
E_TXEN: R1#5.1 U1#5.2(TXEN) ; port INT.E_TXEN  [project net ETH.E_TXEN]
ETH#.RX_N: R9#2.1 U1#5.30(TPRX-) ; port EXT.RX_N
ETH#.RX_P: R8#2.1 U1#5.31(TPRX+) ; port EXT.RX_P
ETH#.TX_N: R14#2.2 U1#5.33(TPTX-) ; port EXT.TX_N
ETH#.TX_P: R15.2 U1#5.34(TPTX+) ; port EXT.TX_P
LK: LED3#1.2(K) R18#2.2 ; port EXT.LINK_K  [project net ETH#.LINK_K]
PWFBOUT: C1#3.1 C2#3.2 C5#2.1 C8.2 L1#2.1 U1#5.32(PWFBOUT) ; port EXT.RX_CT, port EXT.TX_CT  [project net ETH#.RX_CT]
RESETB_E: R19.1 U1#5.42(RESETB) ; port INT.E_RESETB_E  [project net ETH.E_RESETB_E]
RXER_U: R11.1 U1#5.24(RXER) U2.6(A3)
S_LED0: R17.1 R18#2.1 U1#5.9(LED0/AD0)
S_LED1: R20#2.2 R22#2.1 U1#5.10(LED1/AD1)
S_LED2: R21.1 R23#2.1 U1#5.12(LED2/PHYAD2)
S_LED3: R24#2.2 R26.1 U1#5.13(LED3/PHYAD3)
S_LED4: R25.1 R27.1 U1#5.15(LED4/PHYAD4)
X1: C6.2 U1#5.46(X1) Y1#1.1(X1)
X2: C7.2 U1#5.47(X2) Y1#1.3(X2)
NetC4#3_1: C4#3.1 R8#2.2 R9#2.2
NetC9_2: C9.2 R14#2.1 R15.1
NetLED2_1: LED2.1(A) R23#2.2
NetLED3#2_1: LED3#2.1(A) R27.2
NetLED4_1: LED4.1(A) R22#2.2
NetR13_1: R13.1 R16.2
NetR13_2: R13.2 U1#5.28(RTSET)

Not connected (* = marked no-connect by the designer): U1#5 27(NC); U2 3(Y4)* 5(Y3)* 7(Y2)* 9(Y1)* 16(Y2)* 18(Y1)*

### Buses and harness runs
bus E_RXD[3..0]
bus E_TXD[3..0]
bus S_LED[4..0]

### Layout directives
net class Ethernet Interface: (no net found under the mark)

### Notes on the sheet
- (near R1#5) 7 * 4k7
- (near U2) Added buffer to ensure config pulldown Rs are effective during power up
- (near U2) LINK
- (near U2) 10M
- (near U2) FULL DUPLEX
- (near U2) COLLISION
- (near U2) 100M

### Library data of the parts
C1#3 C10 = D-101-0007: as C1_FP on sheet FPGA_Bypass_1V2
C2#3 C3#3 C4#3 C5#2 C8 C9 C11-C15 = D-101-0045: Capacitor, Ceramic, 0.1uF 25V 0402 (1005); Dielectric: X7R; Polarity: Non-Polarized; Tolerance: 10 %
C6 C7 = D-101-0059: Capacitor, Ceramic, 22pF 5% 50V 0402 (1005) COG; Polarity: Non-Polarized
L1#2 L2 = D-102-0006: Inductor, Coil 22uH  1210 (3225) LQH32CN220K21L; Max Input Current: mA
LED2 = D-153-0007: Brightness: 120mcd; Color: Yellow/Amber; Peak Wave Length: nm
LED3#1 LED4 = D-153-0002: Brightness: 50mcd; Peak Wave Length: nm
LED3#2 = D-153-0009: LED, Red 0603 (1608) 63mCd; Peak Wave Length: 630nm
LED6 = D-153-0006: Brightness: 200mcd; Peak Wave Length: nm
R1#5 R2#5 R3#5 R4#3 R5#2 R6#2 R7#2 R10#2 R11 R12#2 R17 R19 R20#2 R21 R24#2 R25 = D-100-0088: as R1#4 on sheet HOST_FPGA_NonIO
R8#2 R9#2 R14#2 R15 = D-100-0017: Resistor, 49R9 1% 0805 (2012); Power Rating: mW; Resistance: 49.9 R
R13 R16 = D-100-0121: Resistor, 1K 1% 0402 (1005); Power Rating: 63 mW
R18#2 R22#2 R23#2 R26 R27 = D-100-0093: Resistor, 470R 1% 0402 (1005); Power Rating: 63 mW
U1#5 = D-221-0000: RTL8201CL-VD, Single-Chip/Single-Port 10/100 Fast Ethernet Phyceiver; Comm Standard: None
U2 = D-205-0000: SN74LVC244ADBR,  Octal Buffer/Driver with 3-State Outputs, 2.0V - 3.6V
Y1#1 = D-103-0030: Crystal, SMD, 25.000000MHz Stab=50ppm 18.0pF; Frequency Stability: 50ppm; Load Capacitance: 18pF; Nominal Operational Voltage: mV

## Sheet TSC_XPT2046.SchDoc: TFT Touchscreen Interface
size A4; Organization: Altium Limited.; Address1: Level 3, 12a Rodborough Rd; Address2: Frenchs Forest 2086; Address3: NSW; Address4: AUSTRALIA; DocumentNumber: 31; SheetNumber: 32; SheetTotal: 78
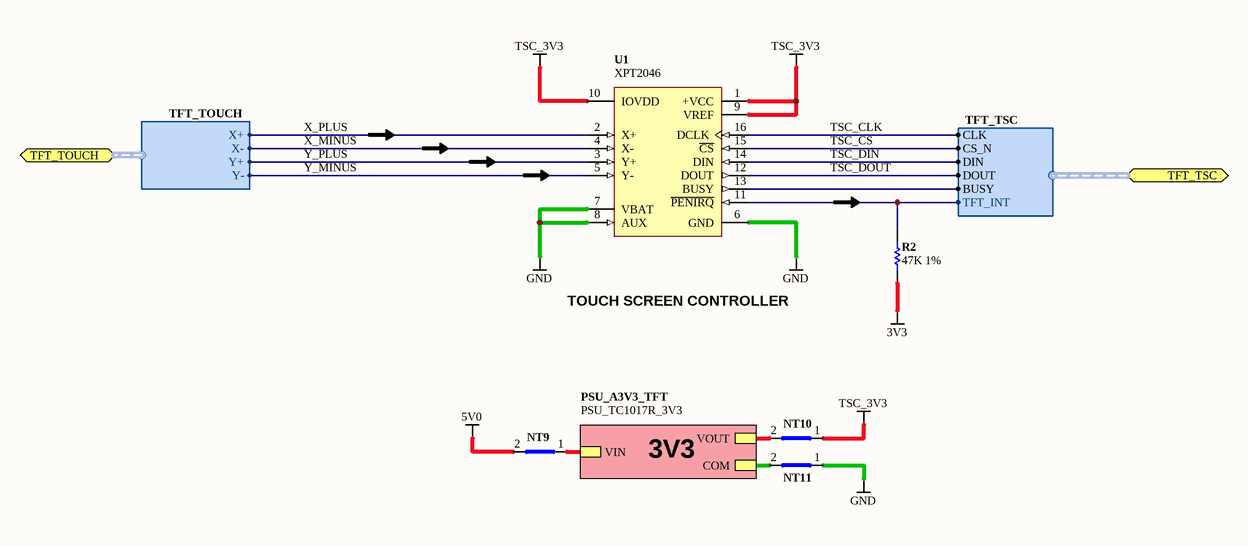
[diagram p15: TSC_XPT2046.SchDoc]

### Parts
(Parts that share a designator on the sheet are numbered #1, #2 ... from top to bottom, then left to right.)
NT9  Net Tie SMT2  [NETTIE-SMT2-31X51]  (value not drawn)  (net tie, no BOM)
NT10  Net Tie SMT2  [NETTIE-SMT2-31X51]  (value not drawn)  (net tie, no BOM)
NT11#2  Net Tie SMT2  [NETTIE-SMT2-31X51]  (value not drawn)  (net tie, no BOM)
R2#6  47K 1%  [RESC1005-STAR]
U1#6  XPT2046  [TSOP65P640-16AN]

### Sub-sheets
PSU_A3V3_TFT = PSU_TC1017R_3V3 (file not in this document): VIN, VOUT, COM

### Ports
TFT_TOUCH (harness TFT_TOUCH), TFT_TSC (harness TFT_TSC)

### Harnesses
TFT_TSC: CLK, CS_N, DIN, DOUT, BUSY, TFT_INT
TFT_TOUCH: X+, X-, Y+, Y-

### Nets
3V3: R2#6.1
5V0: NT9.2(Net2)
GND: NT11#2.1(Net1) U1#6.6(GND) U1#6.7(VBAT) U1#6.8(AUX)
TSC_3V3: NT10.1(Net1) U1#6.1(+VCC) U1#6.9(VREF) U1#6.10(IOVDD)
TFT_TSC.BUSY: U1#6.13(BUSY) ; port TFT_TSC.BUSY
TFT_TSC.TFT_INT: R2#6.2 U1#6.11(~{PENIRQ}) ; port TFT_TSC.TFT_INT
TSC_CLK: U1#6.16(DCLK) ; port TFT_TSC.CLK  [project net TFT_TSC.CLK]
TSC_CS: U1#6.15(~{CS}) ; port TFT_TSC.CS_N  [project net TFT_TSC.CS_N]
TSC_DIN: U1#6.14(DIN) ; port TFT_TSC.DIN  [project net TFT_TSC.DIN]
TSC_DOUT: U1#6.12(DOUT) ; port TFT_TSC.DOUT  [project net TFT_TSC.DOUT]
X_MINUS: U1#6.4(X-) ; port TFT_TOUCH.X-  [project net TFT_TOUCH.X-]
X_PLUS: U1#6.2(X+) ; port TFT_TOUCH.X+  [project net TFT_TOUCH.X+]
Y_MINUS: U1#6.5(Y-) ; port TFT_TOUCH.Y-  [project net TFT_TOUCH.Y-]
Y_PLUS: U1#6.3(Y+) ; port TFT_TOUCH.Y+  [project net TFT_TOUCH.Y+]
NetNT9_1: NT9.1(Net1) ; sheet PSU_A3V3_TFT/VIN
NetNT10_2: NT10.2(Net2) ; sheet PSU_A3V3_TFT/VOUT
NetNT11#2_2: NT11#2.2(Net2) ; sheet PSU_A3V3_TFT/COM

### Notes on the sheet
- TOUCH SCREEN CONTROLLER
- 3V3

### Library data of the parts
NT9 NT10 NT11#2 = D-002-0003: as NT1 on sheet USB_CY7C68001-56LFC
R2#6 = D-100-0092: Resistor, 47K 1% 0402 (1005); Power Rating: 63 mW
U1#6 = D-202-0006: XPT2046, Touch Screen Controller; Supply Voltage: 2.7 to 5.5 V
